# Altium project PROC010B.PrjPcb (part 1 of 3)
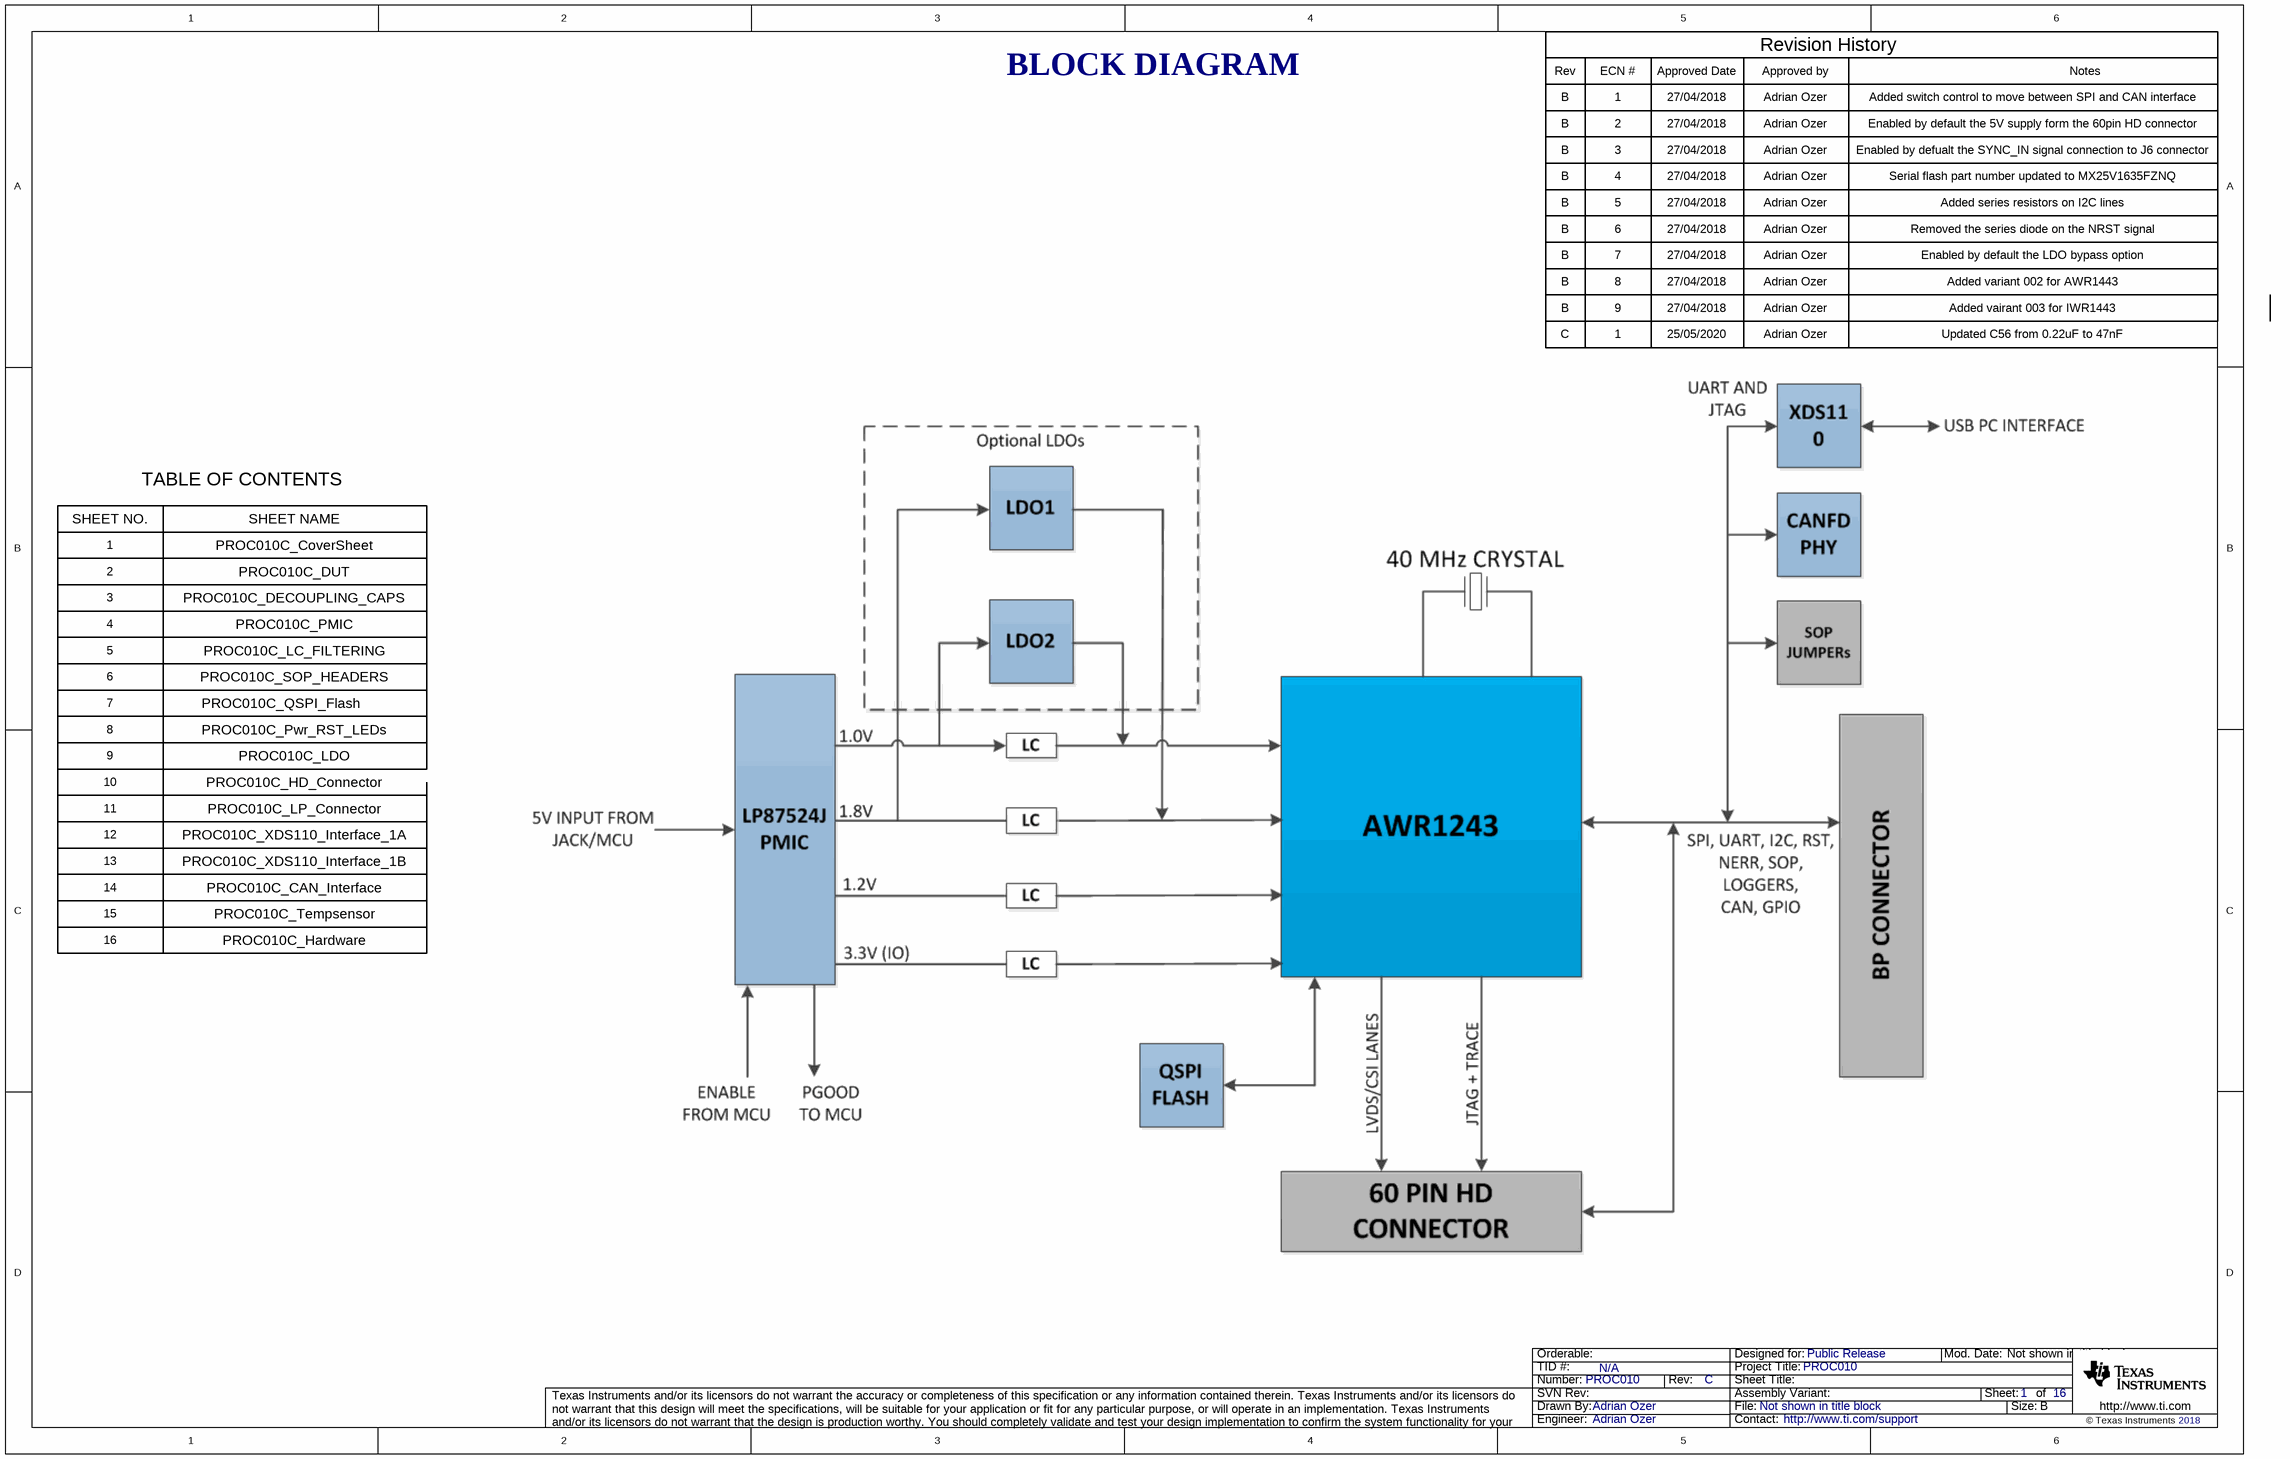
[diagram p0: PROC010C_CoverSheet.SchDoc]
TID: N/A; TechSupport: http://www.ti.com/support; SCH_Rev: C; PRJ_Title: PROC010; PRJ_Number: PROC010; PRJ_Engineer: Adrian Ozer; PRJ_Customer: Public Release; PCB_Rev: B; PCB_Layout: Tessolve; CopyrightYear: 2018
16 sheets, 385 parts. Net scope: flat (ports and power ports of the same name join across sheets).
Board file: PROC010B_PCB.PcbDoc
Sheets:
  PROC010C_CoverSheet.SchDoc
  PROC010C_DUT_Reference.SchDoc
  PROC010C_Decoupling_Caps_Reference.SchDoc
  PROC010C_PMIC_Reference.SchDoc
  PROC010C_LC_Filtering_Reference.SchDoc
  PROC010C_SOP_Headers_Reference.SchDoc
  PROC010C_QSPI_Flash_Reference.SchDoc
  PROC010C_Pwr_RST_LEDs.SchDoc
  PROC010C_LDO.SchDoc
  PROC010C_HD Connector.SchDoc
  PROC010C_LP Connector.SchDoc
  PROC010C_XDS110 Interface_1A.SchDoc
  PROC010C_XDS110 Interface_1B.SchDoc
  PROC010C_CAN Interface.SchDoc
  PROC010C_Tempsensor.SchDoc
  PROC010C_Hardware.SchDoc

## Sheet PROC010C_CoverSheet.SchDoc
size 431 x 279 mm; Date: Not shown in title block; ApprovedBy: Not shown in title block; CheckedBy: Not shown in title block; Author: Not shown in title block; CompanyName: Not shown in title block; DrawnBy: Adrian Ozer; Engineer: Not shown in title block; Organization: Not shown in title block; Address1: Not shown in title block; Address2: Not shown in title block; Address3: Not shown in title block; Address4: Not shown in title block; DocumentNumber: 1; Revision: Use project parameter SCH_Rev; SheetNumber: 1; SheetTotal: 16; PageSetup: Record=PageOptions¦CenterHorizontal=True¦CenterVertical=True¦PrintScale=1.00¦XCorrection=1.00¦YCorrection=1.00¦PrintKind=0¦BorderSize=5000000¦LeftOffset=0¦BottomOffset=0¦Orientation=2¦PaperLength=1000¦PaperWidth=1000¦Scale=100¦PaperSource=15¦PrintQuality=600¦MediaType=1¦DitherType=10¦PaperKind=Letter¦PrintScaleMode=1

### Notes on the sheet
- BLOCK DIAGRAM
- Rev
- B
- ECN #
- 1
- Approved Date
- 27/04/2018
- Approved by
- Adrian Ozer
- Revision History
- Added switch control to move between SPI and CAN interface
- Notes
- 2
- 3
- Enabled by default the 5V supply form the 60pin HD connector
- Enabled by defualt the SYNC_IN signal connection to J6 connector
- 4
- 5
- 6
- Serial flash part number updated to MX25V1635FZNQ
- Added series resistors on I2C lines
- Removed the series diode on the NRST signal
- 7
- 8
- Enabled by default the LDO bypass option
- Added variant 002 for AWR1443
- C
- 9
- 25/05/2020
- Added vairant 003 for IWR1443
- Updated C56 from 0.22uF to 47nF
- TABLE OF CONTENTS
- SHEET NO.
- SHEET NAME
- PROC010C_CoverSheet
- PROC010C_DUT
- PROC010C_DECOUPLING_CAPS
- PROC010C_PMIC
- PROC010C_LC_FILTERING
- PROC010C_SOP_HEADERS
- PROC010C_QSPI_Flash
- PROC010C_Pwr_RST_LEDs
- PROC010C_LDO
- 11
- 10
- PROC010C_HD_Connector
- PROC010C_LP_Connector
- 12
- 13
- 14
- PROC010C_XDS110_Interface_1A
- PROC010C_XDS110_Interface_1B
- PROC010C_CAN_Interface
- 15
- 16
- PROC010C_Tempsensor
- PROC010C_Hardware

## Sheet PROC010C_DUT_Reference.SchDoc
size 431 x 279 mm; Date: Not shown in title block; ApprovedBy: Not shown in title block; CheckedBy: Not shown in title block; Author: Not shown in title block; CompanyName: Not shown in title block; DrawnBy: Adrian Ozer; Engineer: Not shown in title block; Organization: Not shown in title block; Address1: Not shown in title block; Address2: Not shown in title block; Address3: Not shown in title block; Address4: Not shown in title block; DocumentNumber: 2; Revision: Use project parameter SCH_Rev; SheetNumber: 2; SheetTotal: 16; PageSetup: Record=PageOptions¦CenterHorizontal=True¦CenterVertical=True¦PrintScale=1.00¦XCorrection=1.00¦YCorrection=1.00¦PrintKind=0¦BorderSize=5000000¦LeftOffset=0¦BottomOffset=0¦Orientation=2¦PaperLength=1000¦PaperWidth=1000¦Scale=100¦PaperSource=15¦PrintQuality=600¦MediaType=1¦DitherType=10¦PaperKind=Letter¦PrintScaleMode=1
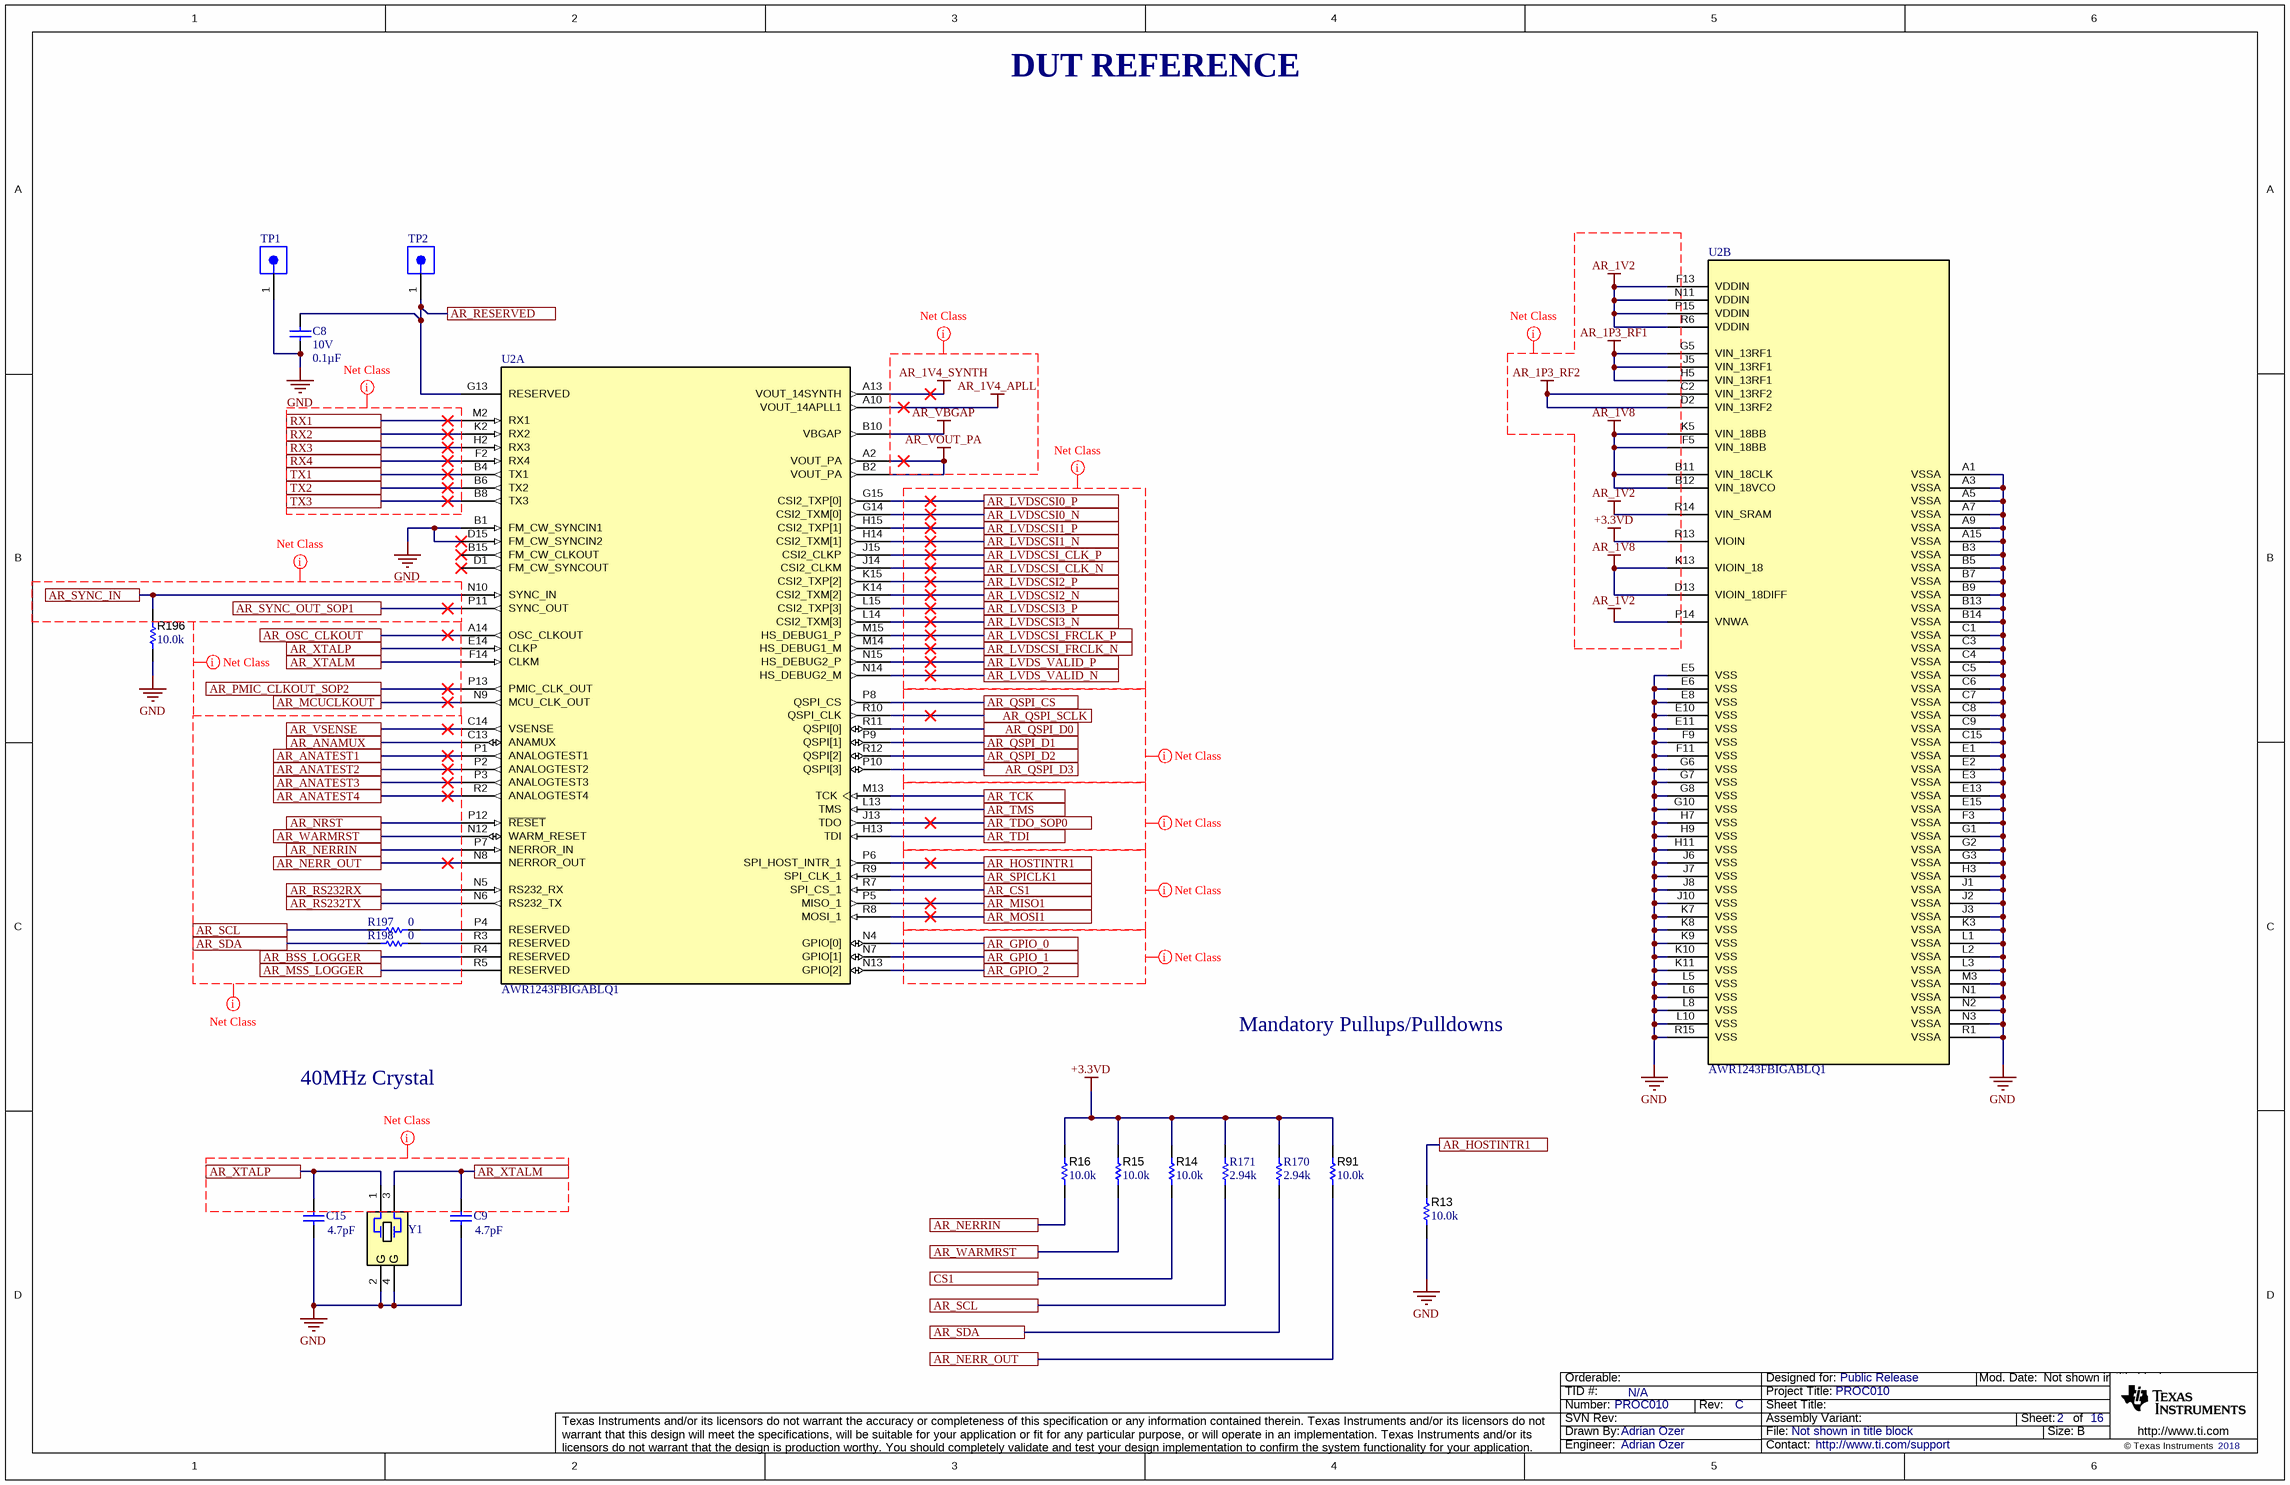
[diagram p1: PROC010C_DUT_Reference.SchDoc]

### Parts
C8  VDC_V: 10V  ValueDisplayed: 0.1µF  [0201_033]  (hidden comment: C0603X7S1A104K030BC)
C9  ValueDisplayed: 4.7pF  [0402]  (hidden comment: GJM1555C1H4R7BB01D)
C15  ValueDisplayed: 4.7pF  [0402]  (hidden comment: GJM1555C1H4R7BB01D)
R13  ValueDisplayed: 10.0k  [0402L]  (hidden comment: CRCW040210K0FKED)
R14  ValueDisplayed: 10.0k  [0402L]  (hidden comment: CRCW040210K0FKED)
R15  ValueDisplayed: 10.0k  [0402L]  (hidden comment: CRCW040210K0FKED)
R16  ValueDisplayed: 10.0k  [0402L]  (hidden comment: CRCW040210K0FKED)
R91  ValueDisplayed: 10.0k  [0402L]  (hidden comment: CRCW040210K0FKED)
R170  ValueDisplayed: 2.94k  [0402]  (hidden comment: CRCW04022K94FKED)
R171  ValueDisplayed: 2.94k  [0402]  (hidden comment: CRCW04022K94FKED)
R196  ValueDisplayed: 10.0k  [0402L]  (hidden comment: CRCW040210K0FKED)
R197  ValueDisplayed: 0  [0201]  (hidden comment: CRCW02010000Z0ED)
R198  ValueDisplayed: 0  [0201]  (hidden comment: CRCW02010000Z0ED)
TP1  TSW-101-17-T-S  [Samtec_TSW-101-17-T-S]  (value not drawn)
TP2  TSW-101-17-T-S  [Samtec_TSW-101-17-T-S]  (value not drawn)
U2  AWR1243FBIGABLQ1  [ABL0161A]  (parts A,B of 2)
Y1  CX3225SA40000D0PTWCC  [Kyocera_CX3225SA]  (value not drawn)

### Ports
AR_ANAMUX, AR_ANATEST1, AR_ANATEST2, AR_ANATEST3, AR_ANATEST4, AR_BSS_LOGGER, AR_CS1, AR_GPIO_0, AR_GPIO_1, AR_GPIO_2, AR_HOSTINTR1, AR_LVDS_VALID_N, AR_LVDS_VALID_P, AR_LVDSCSI0_N, AR_LVDSCSI0_P, AR_LVDSCSI1_N, AR_LVDSCSI1_P, AR_LVDSCSI2_N, AR_LVDSCSI2_P, AR_LVDSCSI3_N, AR_LVDSCSI3_P, AR_LVDSCSI_CLK_N, AR_LVDSCSI_CLK_P, AR_LVDSCSI_FRCLK_N, AR_LVDSCSI_FRCLK_P, AR_MCUCLKOUT, AR_MISO1, AR_MOSI1, AR_MSS_LOGGER, AR_NERR_OUT, AR_NERRIN, AR_NRST, AR_OSC_CLKOUT, AR_PMIC_CLKOUT_SOP2, AR_QSPI_CS, AR_QSPI_D0, AR_QSPI_D1, AR_QSPI_D2, AR_QSPI_D3, AR_QSPI_SCLK, AR_RESERVED, AR_RS232RX, AR_RS232TX, AR_SCL, AR_SDA, AR_SPICLK1, AR_SYNC_IN, AR_SYNC_OUT_SOP1, AR_TCK, AR_TDI, AR_TDO_SOP0, AR_TMS, AR_VSENSE, AR_WARMRST, AR_XTALM, AR_XTALP, CS1, RX1, RX2, RX3, RX4, TX1, TX2, TX3

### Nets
+3.3VD: R14.2 R15.2 R16.2 R91.2 R170.2 R171.2 U2.R13(VIOIN)
AR_1P3_RF1: U2.G5(VIN_13RF1) U2.H5(VIN_13RF1) U2.J5(VIN_13RF1)
AR_1P3_RF2: U2.C2(VIN_13RF2) U2.D2(VIN_13RF2)
AR_1V2: U2.F13(VDDIN) U2.N11(VDDIN) U2.P14(VNWA) U2.P15(VDDIN) U2.R6(VDDIN) U2.R14(VIN_SRAM)
AR_1V4_APLL: U2.A10(VOUT_14APLL1)
AR_1V4_SYNTH: U2.A13(VOUT_14SYNTH)
AR_1V8: U2.B11(VIN_18CLK) U2.B12(VIN_18VCO) U2.D13(VIOIN_18DIFF) U2.F5(VIN_18BB) U2.K5(VIN_18BB) U2.K13(VIOIN_18)
AR_VBGAP: U2.B10(VBGAP)
AR_VOUT_PA: U2.A2(VOUT_PA) U2.B2(VOUT_PA)
GND: C8.2 C9.2 C15.1 R13.1 R196.1 TP1.1 U2.A1(VSSA) U2.A3(VSSA) U2.A5(VSSA) U2.A7(VSSA) U2.A9(VSSA) U2.A15(VSSA) U2.B1(FM_CW_SYNCIN1) U2.B3(VSSA) U2.B5(VSSA) U2.B7(VSSA) U2.B9(VSSA) U2.B13(VSSA) U2.B14(VSSA) U2.C1(VSSA) U2.C3(VSSA) U2.C4(VSSA) U2.C5(VSSA) U2.C6(VSSA) U2.C7(VSSA) U2.C8(VSSA) U2.C9(VSSA) U2.C15(VSSA) U2.D15(FM_CW_SYNCIN2) U2.E1(VSSA) U2.E2(VSSA) U2.E3(VSSA) U2.E5(VSS) U2.E6(VSS) U2.E8(VSS) U2.E10(VSS) U2.E11(VSS) U2.E13(VSSA) U2.E15(VSSA) U2.F3(VSSA) U2.F9(VSS) U2.F11(VSS) U2.G1(VSSA) U2.G2(VSSA) U2.G3(VSSA) U2.G6(VSS) U2.G7(VSS) U2.G8(VSS) U2.G10(VSS) U2.H3(VSSA) U2.H7(VSS) U2.H9(VSS) U2.H11(VSS) U2.J1(VSSA) U2.J2(VSSA) U2.J3(VSSA) U2.J6(VSS) U2.J7(VSS) U2.J8(VSS) U2.J10(VSS) U2.K3(VSSA) U2.K7(VSS) U2.K8(VSS) U2.K9(VSS) U2.K10(VSS) U2.K11(VSS) U2.L1(VSSA) U2.L2(VSSA) U2.L3(VSSA) U2.L5(VSS) U2.L6(VSS) U2.L8(VSS) U2.L10(VSS) U2.M3(VSSA) U2.N1(VSSA) U2.N2(VSSA) U2.N3(VSSA) U2.R1(VSSA) U2.R15(VSS) Y1.2(GND) Y1.4(GND)
AR_ANAMUX: U2.C13(ANAMUX) ; port AR_ANAMUX
AR_ANATEST1: U2.P1(ANALOGTEST1) ; port AR_ANATEST1
AR_ANATEST2: U2.P2(ANALOGTEST2) ; port AR_ANATEST2
AR_ANATEST3: U2.P3(ANALOGTEST3) ; port AR_ANATEST3
AR_ANATEST4: U2.R2(ANALOGTEST4) ; port AR_ANATEST4
AR_BSS_LOGGER: U2.R4(RESERVED) ; port AR_BSS_LOGGER
AR_CS1: U2.R7(SPI_CS_1) ; port AR_CS1
AR_GPIO_0: U2.N4(GPIO[0]) ; port AR_GPIO_0
AR_GPIO_1: U2.N7(GPIO[1]) ; port AR_GPIO_1
AR_GPIO_2: U2.N13(GPIO[2]) ; port AR_GPIO_2
AR_HOSTINTR1: R13.2 U2.P6(SPI_HOST_INTR_1) ; port AR_HOSTINTR1
AR_LVDS_VALID_N: U2.N14(HS_DEBUG2_M) ; port AR_LVDS_VALID_N
AR_LVDS_VALID_P: U2.N15(HS_DEBUG2_P) ; port AR_LVDS_VALID_P
AR_LVDSCSI0_N: U2.G14(CSI2_TXM[0]) ; port AR_LVDSCSI0_N
AR_LVDSCSI0_P: U2.G15(CSI2_TXP[0]) ; port AR_LVDSCSI0_P
AR_LVDSCSI1_N: U2.H14(CSI2_TXM[1]) ; port AR_LVDSCSI1_N
AR_LVDSCSI1_P: U2.H15(CSI2_TXP[1]) ; port AR_LVDSCSI1_P
AR_LVDSCSI2_N: U2.K14(CSI2_TXM[2]) ; port AR_LVDSCSI2_N
AR_LVDSCSI2_P: U2.K15(CSI2_TXP[2]) ; port AR_LVDSCSI2_P
AR_LVDSCSI3_N: U2.L14(CSI2_TXM[3]) ; port AR_LVDSCSI3_N
AR_LVDSCSI3_P: U2.L15(CSI2_TXP[3]) ; port AR_LVDSCSI3_P
AR_LVDSCSI_CLK_N: U2.J14(CSI2_CLKM) ; port AR_LVDSCSI_CLK_N
AR_LVDSCSI_CLK_P: U2.J15(CSI2_CLKP) ; port AR_LVDSCSI_CLK_P
AR_LVDSCSI_FRCLK_N: U2.M14(HS_DEBUG1_M) ; port AR_LVDSCSI_FRCLK_N
AR_LVDSCSI_FRCLK_P: U2.M15(HS_DEBUG1_P) ; port AR_LVDSCSI_FRCLK_P
AR_MCUCLKOUT: U2.N9(MCU_CLK_OUT) ; port AR_MCUCLKOUT
AR_MISO1: U2.P5(MISO_1) ; port AR_MISO1
AR_MOSI1: U2.R8(MOSI_1) ; port AR_MOSI1
AR_MSS_LOGGER: U2.R5(RESERVED) ; port AR_MSS_LOGGER
AR_NERR_OUT: R91.1 U2.N8(NERROR_OUT) ; port AR_NERR_OUT
AR_NERRIN: R16.1 U2.P7(NERROR_IN) ; port AR_NERRIN
AR_NRST: U2.P12(~{RESET}) ; port AR_NRST
AR_OSC_CLKOUT: U2.A14(OSC_CLKOUT) ; port AR_OSC_CLKOUT
AR_PMIC_CLKOUT_SOP2: U2.P13(PMIC_CLK_OUT) ; port AR_PMIC_CLKOUT_SOP2
AR_QSPI_CS: U2.P8(QSPI_CS) ; port AR_QSPI_CS
AR_QSPI_D0: U2.R11(QSPI[0]) ; port AR_QSPI_D0
AR_QSPI_D1: U2.P9(QSPI[1]) ; port AR_QSPI_D1
AR_QSPI_D2: U2.R12(QSPI[2]) ; port AR_QSPI_D2
AR_QSPI_D3: U2.P10(QSPI[3]) ; port AR_QSPI_D3
AR_QSPI_SCLK: U2.R10(QSPI_CLK) ; port AR_QSPI_SCLK
AR_RESERVED: C8.1 TP2.1 U2.G13(RESERVED) ; port AR_RESERVED
AR_RS232RX: U2.N5(RS232_RX) ; port AR_RS232RX
AR_RS232TX: U2.N6(RS232_TX) ; port AR_RS232TX
AR_SCL: R171.1 R197.1 ; port AR_SCL
AR_SDA: R170.1 R198.1 ; port AR_SDA
AR_SPICLK1: U2.R9(SPI_CLK_1) ; port AR_SPICLK1
AR_SYNC_IN: R196.2 U2.N10(SYNC_IN) ; port AR_SYNC_IN
AR_SYNC_OUT_SOP1: U2.P11(SYNC_OUT) ; port AR_SYNC_OUT_SOP1
AR_TCK: U2.M13(TCK) ; port AR_TCK
AR_TDI: U2.H13(TDI) ; port AR_TDI
AR_TDO_SOP0: U2.J13(TDO) ; port AR_TDO_SOP0
AR_TMS: U2.L13(TMS) ; port AR_TMS
AR_VSENSE: U2.C14(VSENSE) ; port AR_VSENSE
AR_WARMRST: R15.1 U2.N12(WARM_RESET) ; port AR_WARMRST
AR_XTALM: C9.1 U2.F14(CLKM) Y1.3 ; port AR_XTALM
AR_XTALP: C15.2 U2.E14(CLKP) Y1.1 ; port AR_XTALP
CS1: R14.1 ; port CS1
RX1: U2.M2(RX1) ; port RX1
RX2: U2.K2(RX2) ; port RX2
RX3: U2.H2(RX3) ; port RX3
RX4: U2.F2(RX4) ; port RX4
TX1: U2.B4(TX1) ; port TX1
TX2: U2.B6(TX2) ; port TX2
TX3: U2.B8(TX3) ; port TX3
NetR197_2: R197.2 U2.P4(RESERVED)
NetR198_2: R198.2 U2.R3(RESERVED)

Not connected (* = marked no-connect by the designer): U2 B15(FM_CW_CLKOUT)* D1(FM_CW_SYNCOUT)*

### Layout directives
net class RF: (no net found under the mark)
net class GENERAL: (no net found under the mark)
net class SPI: (no net found under the mark)
net class PWR: +3.3VD, AR_1P3_RF1, AR_1P3_RF2, AR_1V2, AR_1V4_APLL, AR_1V4_SYNTH, AR_1V8, AR_VBGAP, AR_VOUT_PA
net class CLK: (no net found under the mark)
net class LVDS: (no net found under the mark)
net class QSPI: (no net found under the mark)
net class JTAG: (no net found under the mark)

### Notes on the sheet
- DUT REFERENCE
- Mandatory Pullups/Pulldowns
- 40MHz Crystal

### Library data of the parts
C8 = CMP-0078219-1: CAP, CERM, 0.1 µF, 10 V,+/- 10%, X7S, 0201; Manufacturer: TDK; TaMin_C: -55°C; Polarized: N; Green_Lifecycle: NRND; SizeAreaWB_mm2: 2.08; Green_REACh: Passed; U/M: EA; Value: 0.1uF; TaMax_C: 125°C; SizeZ_mm: 0.33; SizeX_mm: 0.6; SizeY_mm: 0.3; Cap_Case: 0201; SizeArea_mm2: 0.18; Cap_F: 100nF; AEC Category: Q200
C9 C15 = CMP-0006367-2: CAP, CERM, 4.7 pF, 50 V, +/- 2%, C0G/NP0, 0402; Manufacturer: MuRata; TaMin_C: -55°C; Polarized: N; SizeAreaWB_mm2: 3; Value1: Unknown; U/M: EA; Value: 4.7pF; TaMax_C: 125°C; SizeZ_mm: 0.6; SizeX_mm: 1; SizeY_mm: 0.5; Value2: 50V; CompType: Capacitor; AEC Category: Q200
R13-R16 R91 = CMP-0025958-3: RES, 10.0 k, 1%, 0.063 W, AEC-Q200 Grade 0, 0402; Manufacturer: Vishay-Dale; Power_W: 63mW; TempCo: 100 ppm/C; Value_Code: 10k0; Value: 10.0k; EIA_Code: E96; Res_ohm: 10k; SizeX_mm: 1; SizeY_mm: 0.5; SizeZ_mm: 0.6; Value2: 0.063W; AEC Qualified: Y; VDC_V: 50V; AEC Category: Q200; AEC Grade: 0
R170 R171 = CMP-0026244-2: RES, 2.94 k, 1%, 0.063 W, AEC-Q200 Grade 0, 0402; Manufacturer: Vishay-Dale; Power_W: 63mW; TempCo: 100 ppm/C; Value_Code: 2k94; Value: 2.94k; EIA_Code: E96; SizeX_mm: 1; SizeY_mm: 0.5; SizeZ_mm: 0.6; Value2: 0.063W; AEC Qualified: Y; VDC_V: 50V; AEC Category: Q200; AEC Grade: 0
R196 = CMP-0025958-3: RES, 10.0 k, 1%, 0.063 W, AEC-Q200 Grade 0, 0402; Manufacturer: Vishay-Dale; Power_W: 63mW; TempCo: 100 ppm/C; Value_Code: 10k0; Value: 10.0k; EIA_Code: E96; Res_ohm: 10k; SizeX_mm: 1; SizeY_mm: 0.5; SizeZ_mm: 0.6; Value2: 0.063W; CompType: Resistor; AEC Qualified: Y; VDC_V: 50V; AEC Category: Q200; AEC Grade: 0
R197 R198 = CMP-0027008-4: RES, 0, 5%, 0.05 W, 0201; Manufacturer: Vishay-Dale; Power_W: 50mW; TempCo: ppm/C; Value_Code: 0000; Value: 0; EIA_Code: E24; SizeX_mm: 0.6; SizeY_mm: 0.3; SizeZ_mm: 0.26; Value2: 0.05W; SizeArea_mm2: 0.18; AEC Qualified: N; AEC Category: Q200
TP1 TP2 = CMP-0055993-1: Header, 100mil, 1x1, Tin, TH; Manufacturer: Samtec; Cert_VDE: N; CNHeader: FALSE; Current_A: 6.3A; Green_Lifecycle: Active; Gender: Male; Cert_CSA: Y; Green_REACh: Passed; Voltage_V: 550V; Row_Count: 1; Pitch_mm: 2.54
U2 = CMP-0081285-1: Single Chip 77 and 79 GHz FMCW Transceiver, ABL0161A (FCBGA-161); Alternate PartNumber: AWR1243FBIGABLRQ1; Alternate Manufacturer: Texas Instruments; SizeAreaWB_mm2: 153.76; SizeZ_mm: 1.17; SizeX_mm: 10.4; SizeArea_mm2: 108.16; CompType: IC; AEC Qualified: N; AEC Category: Q200
Y1 = CMP-0004694-3: Crystal, 40 MHz, 8pF, SMD; Manufacturer: Kyocera; TaMin_C: -40°C; Frequency Stability: +/-200ppm; SizeAreaWB_mm2: 14.7; Frequency_Fixed: 40MHz; TaMax_C: 125°C; SizeZ_mm: 0.8; SizeX_mm: 2.5; SizeY_mm: 3.2; SizeArea_mm2: 8

## Sheet PROC010C_Decoupling_Caps_Reference.SchDoc
size 431 x 279 mm; Date: Not shown in title block; ApprovedBy: Not shown in title block; CheckedBy: Not shown in title block; Author: Not shown in title block; CompanyName: Not shown in title block; DrawnBy: Adrian Ozer; Engineer: Not shown in title block; Organization: Not shown in title block; Address1: Not shown in title block; Address2: Not shown in title block; Address3: Not shown in title block; Address4: Not shown in title block; DocumentNumber: 3; Revision: Use project parameter SCH_Rev; SheetNumber: 3; SheetTotal: 16; PageSetup: Record=PageOptions¦CenterHorizontal=True¦CenterVertical=True¦PrintScale=1.00¦XCorrection=1.00¦YCorrection=1.00¦PrintKind=0¦BorderSize=5000000¦LeftOffset=0¦BottomOffset=0¦Orientation=2¦PaperLength=1000¦PaperWidth=1000¦Scale=100¦PaperSource=15¦PrintQuality=600¦MediaType=1¦DitherType=10¦PaperKind=Letter¦PrintScaleMode=1
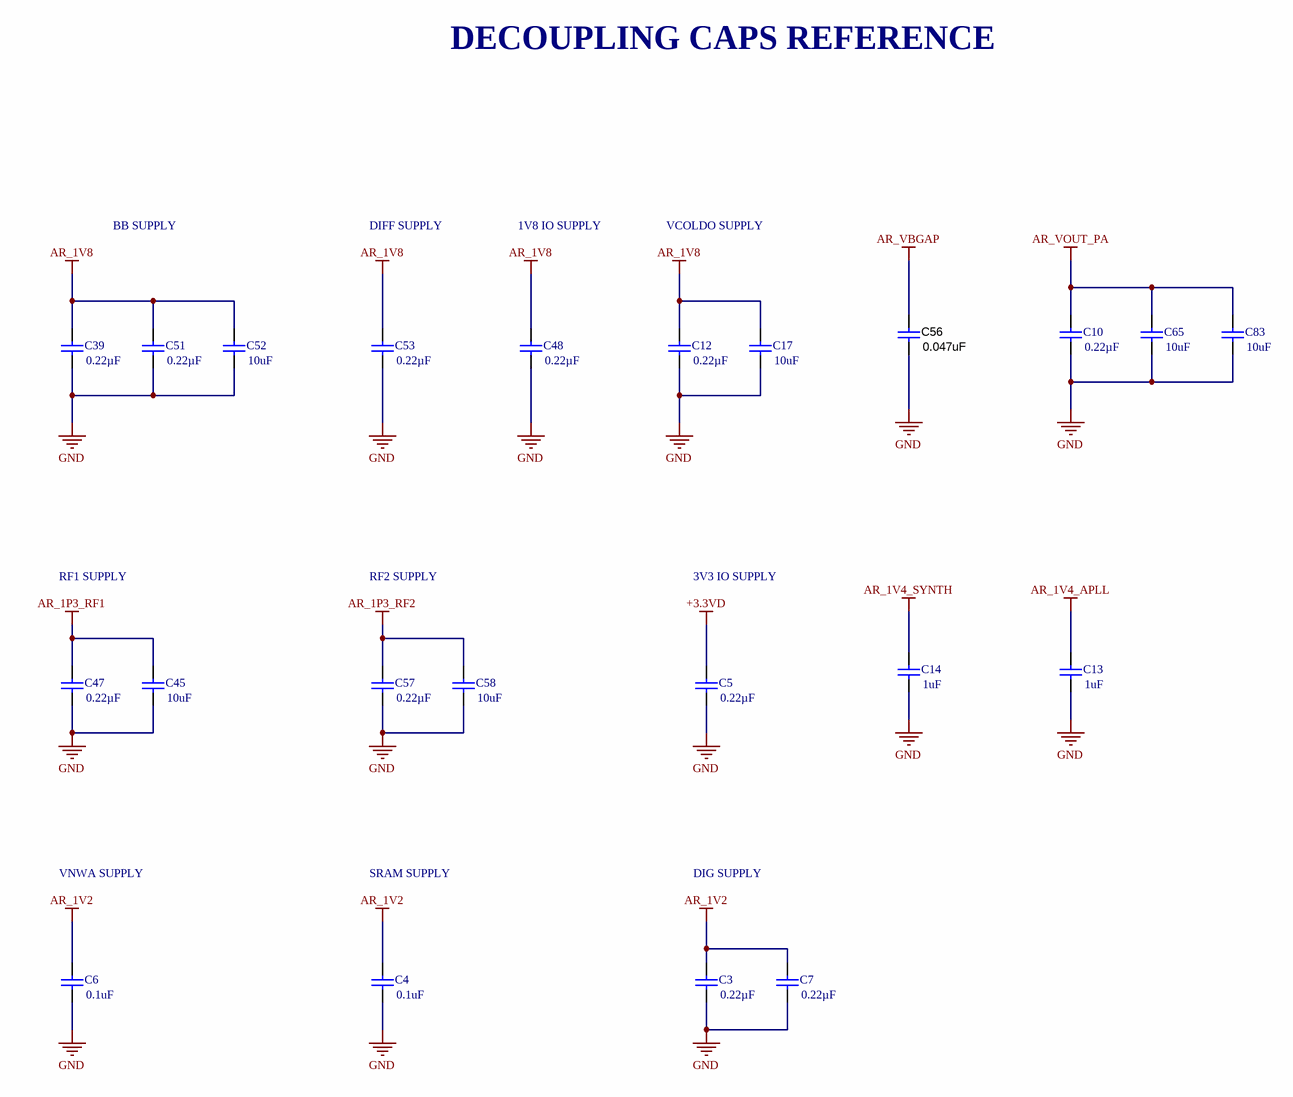
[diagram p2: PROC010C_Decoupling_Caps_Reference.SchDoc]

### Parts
C3  ValueDisplayed: 0.22µF  [0402L]  (hidden comment: GCM155R71C224KE02D)
C4  ValueDisplayed: 0.1uF  [0402L]  (hidden comment: GCM155R71C104KA55D)
C5  ValueDisplayed: 0.22µF  [0402L]  (hidden comment: GCM155R71C224KE02D)
C6  ValueDisplayed: 0.1uF  [0402]  (hidden comment: GCM155R71C104KA55D)
C7  ValueDisplayed: 0.22µF  [0402L]  (hidden comment: GCM155R71C224KE02D)
C10  ValueDisplayed: 0.22µF  [0402]  (hidden comment: GCM155R71C224KE02D)
C12  ValueDisplayed: 0.22µF  [0402]  (hidden comment: GCM155R71C224KE02D)
C13  ValueDisplayed: 1uF  [0603]  (hidden comment: GCM188R71C105KA64D)
C14  ValueDisplayed: 1uF  [0603]  (hidden comment: GCM188R71C105KA64D)
C17  ValueDisplayed: 10uF  [0805_HV]  (hidden comment: GCM21BR71A106KE22L)
C39  ValueDisplayed: 0.22µF  [0402L]  (hidden comment: GCM155R71C224KE02D)
C45  ValueDisplayed: 10uF  [0805_HV1]  (hidden comment: GCM21BR71A106KE22L)
C47  ValueDisplayed: 0.22µF  [0402L]  (hidden comment: GCM155R71C224KE02D)
C48  ValueDisplayed: 0.22µF  [0402]  (hidden comment: GCM155R71C224KE02D)
C51  ValueDisplayed: 0.22µF  [0402]  (hidden comment: GCM155R71C224KE02D)
C52  ValueDisplayed: 10uF  [0805_HV]  (hidden comment: GCM21BR71A106KE22L)
C53  ValueDisplayed: 0.22µF  [0402]  (hidden comment: GCM155R71C224KE02D)
C56  ValueDisplayed: 0.047uF  [0402]  (hidden comment: CGA2B3X7R1H473K050BB)
C57  ValueDisplayed: 0.22µF  [0402]  (hidden comment: GCM155R71C224KE02D)
C58  ValueDisplayed: 10uF  [0805]  (hidden comment: GCM21BR71A106KE22L)
C65  ValueDisplayed: 10uF  [0805_HV]  (hidden comment: GCM21BR71A106KE22L)
C83  ValueDisplayed: 10uF  [0805_HV]  (hidden comment: GCM21BR71A106KE22L)

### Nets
+3.3VD: C5.1
AR_1P3_RF1: C45.1 C47.1
AR_1P3_RF2: C57.1 C58.1
AR_1V2: C3.1 C4.1 C6.1 C7.1
AR_1V4_APLL: C13.1
AR_1V4_SYNTH: C14.1
AR_1V8: C12.1 C17.1 C39.1 C48.1 C51.1 C52.1 C53.1
AR_VBGAP: C56.1
AR_VOUT_PA: C10.1 C65.1 C83.1
GND: C3.2 C4.2 C5.2 C6.2 C7.2 C10.2 C12.2 C13.2 C14.2 C17.2 C39.2 C45.2 C47.2 C48.2 C51.2 C52.2 C53.2 C56.2 C57.2 C58.2 C65.2 C83.2

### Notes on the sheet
- DECOUPLING CAPS REFERENCE
- BB SUPPLY
- DIFF SUPPLY
- 1V8 IO SUPPLY
- VCOLDO SUPPLY
- RF1 SUPPLY
- RF2 SUPPLY
- 3V3 IO SUPPLY
- VNWA SUPPLY
- SRAM SUPPLY
- DIG SUPPLY

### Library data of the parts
C3 C5 C7 C39 C47 = CMP-0078265-1: CAP, CERM, 0.22 µF, 16 V,+/- 10%, X7R, AEC-Q200 Grade 1, 0402; Manufacturer: MuRata; TaMin_C: -55°C; Polarized: N; SizeAreaWB_mm2: 3; U/M: EA; Value: 0.22uF; TaMax_C: 125°C; SizeZ_mm: 0.6; SizeX_mm: 1; SizeY_mm: 0.5; Cap_Case: 0402; Value2: 16V; CompType: Capacitor; AEC Qualified: Y; Cap_F: 220nF; AEC Category: Q200
C4 = CMP-0006351-2: CAP, CERM, 0.1 uF, 16 V, +/- 10%, X7R, 0402; Manufacturer: MuRata; TaMin_C: -55°C; Polarized: N; SizeAreaWB_mm2: 3; Value1: Unknown; U/M: EA; Value: 0.1uF; TaMax_C: 125°C; SizeZ_mm: 0.6; SizeX_mm: 1; SizeY_mm: 0.5; Cap_Case: 0402; Value2: 16V; CompType: Capacitor; Cap_F: 100nF; AEC Category: Q200
C6 = CMP-0006351-2: CAP, CERM, 0.1 uF, 16 V, +/- 10%, X7R, 0402; Manufacturer: MuRata; TaMin_C: -55°C; Polarized: N; SizeAreaWB_mm2: 3; Value1: Unknown; U/M: EA; Value: 0.1uF; TaMax_C: 125°C; SizeZ_mm: 0.6; SizeX_mm: 1; SizeY_mm: 0.5; Value2: 16V; Cap_F: 100nF; AEC Category: Q200
C10 C12 C48 C51 C53 C57 = CMP-0078265-1: CAP, CERM, 0.22 µF, 16 V,+/- 10%, X7R, AEC-Q200 Grade 1, 0402; Manufacturer: MuRata; TaMin_C: -55°C; Polarized: N; SizeAreaWB_mm2: 3; U/M: EA; Value: 0.22uF; TaMax_C: 125°C; SizeZ_mm: 0.6; SizeX_mm: 1; SizeY_mm: 0.5; Value2: 16V; AEC Qualified: Y; Cap_F: 220nF; AEC Category: Q200
C13 C14 = CMP-0007136-5: CAP, CERM, 1 uF, 16 V, +/- 10%, X7R, AEC-Q200 Grade 1, 0603; Manufacturer: MuRata; TaMin_C: -55°C; Polarized: N; SizeAreaWB_mm2: 4.68; Value1: Unknown; U/M: EA; Value: 1uF; TaMax_C: 125°C; SizeZ_mm: 1; SizeX_mm: 1.6; SizeY_mm: 0.8; Value2: 16V; SizeArea_mm2: 1.28; AEC Qualified: Y; Cap_F: 1µF; AEC Category: Q200
C17 C52 C65 C83 = CMP-0008017-2: CAP, CERM, 10 uF, 10 V, +/- 10%, X7R, 0805; Manufacturer: MuRata; TaMin_C: -55°C; Polarized: N; SizeAreaWB_mm2: 6.75; Value1: Unknown; U/M: EA; Value: 10uF; TaMax_C: 125°C; SizeZ_mm: 1.45; SizeX_mm: 2; SizeY_mm: 1.25; Cap_Case: 0805; Value2: 10V; SizeArea_mm2: 2.5; Cap_F: 10µF; AEC Category: Q200
C45 = CMP-0008017-2: CAP, CERM, 10 uF, 10 V, +/- 10%, X7R, 0805; Manufacturer: MuRata; TaMin_C: -55°C; Polarized: N; SizeAreaWB_mm2: 6.75; Value1: Unknown; U/M: EA; Value: 10uF; TaMax_C: 125°C; SizeZ_mm: 1.45; SizeX_mm: 2; SizeY_mm: 1.25; Cap_Case: 0805; Value2: 10V; SizeArea_mm2: 2.5; CompType: Capacitor; Cap_F: 10µF; AEC Category: Q200
C56 = CMP-0006330-2: CAP, CERM, 0.047 uF, 50 V, +/- 10%, X7R, AEC-Q200 Grade 1, 0402; Manufacturer: TDK; TaMin_C: -55°C; ESR_ohm: 0.06407; Polarized: N; SizeAreaWB_mm2: 3; Value1: 0.06407 ohm; U/M: EA; TaMax_C: 125°C; SizeZ_mm: 0.6; SizeX_mm: 1; SizeY_mm: 0.5; Value2: 50V; AEC Qualified: Y; Cap_F: 47nF; IRMS_A: 646.122mA; AEC Category: Q200
C58 = CMP-0008017-2: CAP, CERM, 10 uF, 10 V, +/- 10%, X7R, 0805; Manufacturer: MuRata; TaMin_C: -55°C; Polarized: N; SizeAreaWB_mm2: 6.75; Value1: Unknown; U/M: EA; Value: 10uF; TaMax_C: 125°C; SizeZ_mm: 1.45; SizeX_mm: 2; SizeY_mm: 1.25; Value2: 10V; SizeArea_mm2: 2.5; CompType: Capacitor; Cap_F: 10µF; AEC Category: Q200

## Sheet PROC010C_PMIC_Reference.SchDoc: PMIC
size 431 x 279 mm; Date: Not shown in title block; ApprovedBy: Not shown in title block; CheckedBy: Not shown in title block; Author: Not shown in title block; CompanyName: Not shown in title block; DrawnBy: Adrian Ozer; Engineer: Not shown in title block; Organization: Not shown in title block; Address1: Not shown in title block; Address2: Not shown in title block; Address3: Not shown in title block; Address4: Not shown in title block; DocumentNumber: 4; Revision: Use project parameter SCH_Rev; SheetNumber: 4; SheetTotal: 16; PageSetup: Record=PageOptions¦CenterHorizontal=True¦CenterVertical=True¦PrintScale=1.00¦XCorrection=1.00¦YCorrection=1.00¦PrintKind=0¦BorderSize=5000000¦LeftOffset=0¦BottomOffset=0¦Orientation=2¦PaperLength=1000¦PaperWidth=1000¦Scale=100¦PaperSource=15¦PrintQuality=600¦MediaType=1¦DitherType=10¦PaperKind=Letter¦PrintScaleMode=1
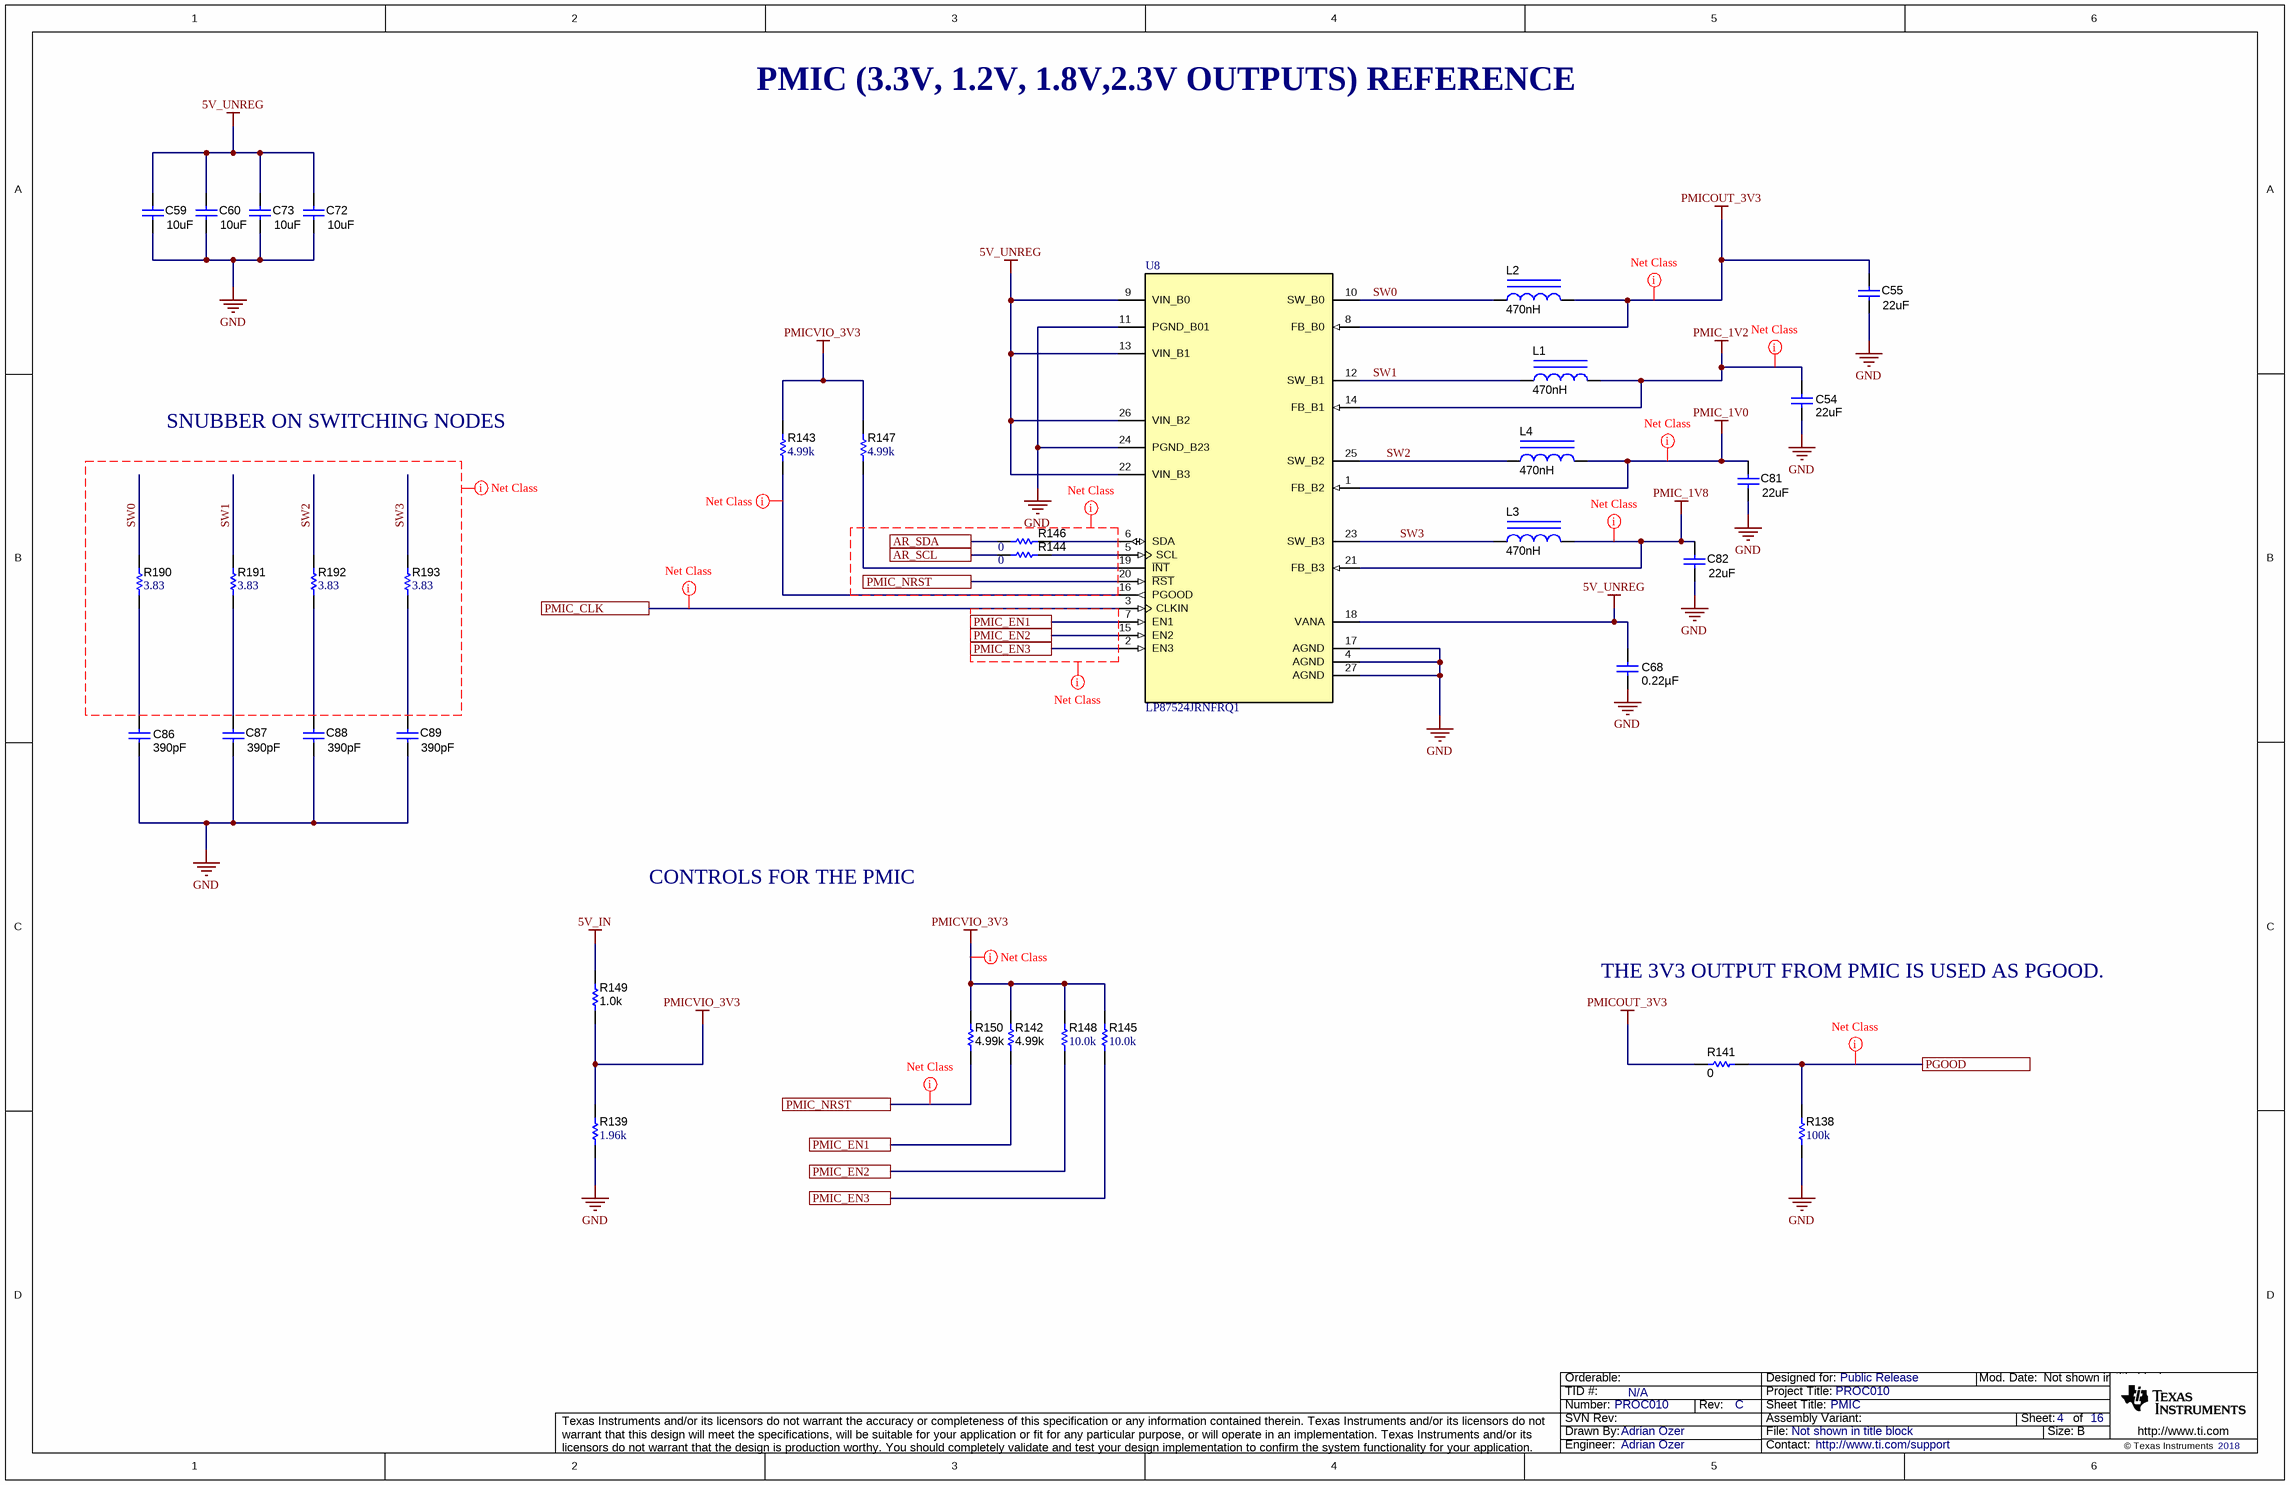
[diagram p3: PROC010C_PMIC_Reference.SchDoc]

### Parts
C54  ValueDisplayed: 22uF  [1206_180]  (hidden comment: GCM31CR71A226KE02)
C55  ValueDisplayed: 22uF  [1206_180]  (hidden comment: GCM31CR71A226KE02)
C59  ValueDisplayed: 10uF  [0805_HV1]  (hidden comment: GCM21BR71A106KE22L)
C60  ValueDisplayed: 10uF  [0805_HV1]  (hidden comment: GCM21BR71A106KE22L)
C68  ValueDisplayed: 0.22µF  [0402L]  (hidden comment: GCM155R71C224KE02D)
C72  ValueDisplayed: 10uF  [0805_HV1]  (hidden comment: GCM21BR71A106KE22L)
C73  ValueDisplayed: 10uF  [0805_HV1]  (hidden comment: GCM21BR71A106KE22L)
C81  ValueDisplayed: 22uF  [1206_180]  (hidden comment: GCM31CR71A226KE02)
C82  ValueDisplayed: 22uF  [1206_180]  (hidden comment: GCM31CR71A226KE02)
C86  ValueDisplayed: 390pF  [0402L]  (hidden comment: CGA2B2NP01H391J050BA)
C87  ValueDisplayed: 390pF  [0402L]  (hidden comment: CGA2B2NP01H391J050BA)
C88  ValueDisplayed: 390pF  [0402L]  (hidden comment: CGA2B2NP01H391J050BA)
C89  ValueDisplayed: 390pF  [0402L]  (hidden comment: CGA2B2NP01H391J050BA)
L1  ValueDisplayed: 470nH  [DFE252012P]  (hidden comment: DFE252012P-R47M=P2)
L2  ValueDisplayed: 470nH  [DFE252012P]  (hidden comment: DFE252012P-R47M=P2)
L3  ValueDisplayed: 470nH  [DFE252012P]  (hidden comment: DFE252012P-R47M=P2)
L4  ValueDisplayed: 470nH  [DFE252012P]  (hidden comment: DFE252012P-R47M=P2)
R138  ValueDisplayed: 100k  [0402L]  (hidden comment: CRCW0402100KFKED)
R139  ValueDisplayed: 1.96k  [0402L]  (hidden comment: CRCW04021K96FKED)
R141  ValueDisplayed: 0  [0402L]  (hidden comment: ERJ-2GE0R00X)
R142  ValueDisplayed: 4.99k  [0402L]  (hidden comment: ERJ-2RKF4991X)
R143  ValueDisplayed: 4.99k  [0402L]  (hidden comment: CRCW04024K99FKED)
R144  ValueDisplayed: 0  [0201_Silk]  (hidden comment: CRCW02010000Z0ED)
R145  ValueDisplayed: 10.0k  [0402L]  (hidden comment: CRCW040210K0FKED)
R146  ValueDisplayed: 0  [0201_Silk]  (hidden comment: CRCW02010000Z0ED)
R147  ValueDisplayed: 4.99k  [0402L]  (hidden comment: CRCW04024K99FKED)
R148  ValueDisplayed: 10.0k  [0402L]  (hidden comment: CRCW040210K0FKED)
R149  ValueDisplayed: 1.0k  [0402L]  (hidden comment: ERJ-2GEJ102X)
R150  ValueDisplayed: 4.99k  [0402L]  (hidden comment: ERJ-2RKF4991X)
R190  ValueDisplayed: 3.83  [0402L]  (hidden comment: CRCW04023R83FKED)
R191  ValueDisplayed: 3.83  [0402L]  (hidden comment: CRCW04023R83FKED)
R192  ValueDisplayed: 3.83  [0402L]  (hidden comment: CRCW04023R83FKED)
R193  ValueDisplayed: 3.83  [0402L]  (hidden comment: CRCW04023R83FKED)
U8  LP87524JRNFRQ1  [RNF0026C]

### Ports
AR_SCL, AR_SDA, PGOOD, PMIC_CLK, PMIC_EN1, PMIC_EN2, PMIC_EN3, PMIC_NRST

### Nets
5V_IN: R149.2
5V_UNREG: C59.2 C60.2 C68.2 C72.2 C73.2 U8.9(VIN_B0) U8.13(VIN_B1) U8.18(VANA) U8.22(VIN_B3) U8.26(VIN_B2)
GND: C54.1 C55.1 C59.1 C60.1 C68.1 C72.1 C73.1 C81.1 C82.1 C86.1 C87.1 C88.1 C89.1 R138.1 R139.1 U8.4(AGND) U8.11(PGND_B01) U8.17(AGND) U8.24(PGND_B23) U8.27(AGND)
PMIC_1V0: C81.2 L4.2 U8.1(FB_B2)
PMIC_1V2: C54.2 L1.2 U8.14(FB_B1)
PMIC_1V8: C82.2 L3.2 U8.21(FB_B3)
PMICOUT_3V3: C55.2 L2.2 R141.1 U8.8(FB_B0)
PMICVIO_3V3: R139.2 R142.2 R143.2 R145.2 R147.2 R148.2 R149.1 R150.1
AR_SCL: R144.1 ; port AR_SCL
AR_SDA: R146.2 ; port AR_SDA
PGOOD: R138.2 R141.2 ; port PGOOD
PMIC_CLK: U8.3(CLKIN) ; port PMIC_CLK
PMIC_EN1: R142.1 U8.7(EN1) ; port PMIC_EN1
PMIC_EN2: R148.1 U8.15(EN2) ; port PMIC_EN2
PMIC_EN3: R145.1 U8.2(EN3) ; port PMIC_EN3
PMIC_NRST: R150.2 U8.20(~{RST}) ; port PMIC_NRST
SW0: L2.1 R190.2 U8.10(SW_B0)
SW1: L1.1 R191.2 U8.12(SW_B1)
SW2: L4.1 R192.2 U8.25(SW_B2)
SW3: L3.1 R193.2 U8.23(SW_B3)
NetC86_2: C86.2 R190.1
NetC87_2: C87.2 R191.1
NetC88_2: C88.2 R192.1
NetC89_2: C89.2 R193.1
NetR143_1: R143.1 U8.16(PGOOD)
NetR144_2: R144.2 U8.5(SCL)
NetR146_1: R146.1 U8.6(SDA)
NetR147_1: R147.1 U8.19(~{INT})

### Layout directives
net class PWR: PGOOD, PMIC_1V0, PMIC_1V2, PMIC_1V8, PMICOUT_3V3, PMICVIO_3V3
net class GENERAL: (no net found under the mark), NetR143_1, PMIC_NRST, SW0, SW1, SW2, SW3
net class CLK: PMIC_CLK

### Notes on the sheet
- PMIC (3.3V, 1.2V, 1.8V,2.3V OUTPUTS) REFERENCE
- SNUBBER ON SWITCHING NODES
- CONTROLS FOR THE PMIC
- THE 3V3 OUTPUT FROM PMIC IS USED AS PGOOD.

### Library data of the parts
C54 = CMP-0008811-2: CAP, CERM, 22 uF, 10 V, +/- 10%, X7R, AEC-Q200 Grade 1, 1206; Manufacturer: MuRata; TaMin_C: -55°C; Polarized: N; SizeAreaWB_mm2: 10.92; Value1: Unknown; U/M: EA; Value: 22uF; TaMax_C: 125°C; SizeZ_mm: 1.8; SizeX_mm: 3.2; SizeY_mm: 1.6; Cap_Case: 1206; Value2: 10V; SizeArea_mm2: 5.12; CompType: Capacitor; AEC Qualified: Y; Cap_F: 22µF; AEC Grade: 1; AEC Category: Q200
C55 C81 C82 = CMP-0008811-2: CAP, CERM, 22 uF, 10 V, +/- 10%, X7R, AEC-Q200 Grade 1, 1206; Manufacturer: MuRata; TaMin_C: -55°C; Polarized: N; SizeAreaWB_mm2: 10.92; Value1: Unknown; U/M: EA; Value: 22uF; TaMax_C: 125°C; SizeZ_mm: 1.8; SizeX_mm: 3.2; SizeY_mm: 1.6; Cap_Case: 1206; Value2: 10V; SizeArea_mm2: 5.12; AEC Qualified: Y; Cap_F: 22µF; AEC Grade: 1; AEC Category: Q200
C59 C60 C72 C73 = CMP-0008017-2: as C45 on sheet PROC010C_Decoupling_Caps_Reference
C68 = CMP-0078265-1: as C3 on sheet PROC010C_Decoupling_Caps_Reference
C86-C89 = CMP-0078223-1: CAP, CERM, 390 pF, 50 V,+/- 5%, C0G/NP0, AEC-Q200 Grade 0, 0402; Manufacturer: TDK; TaMin_C: -55°C; Polarized: N; SizeAreaWB_mm2: 3; U/M: EA; Value: 390pF; TaMax_C: 150°C; SizeZ_mm: 0.6; SizeX_mm: 1; SizeY_mm: 0.5; Cap_Case: 0402; Value2: 50V; AEC Qualified: Y; AEC Grade: 0; AEC Category: Q200
L1-L4 = CMP-0058946-1: Inductor, Shielded, 470 nH, 4.7 A, 0.021 ohm, SMD; Manufacturer: MuRata Toko; Isat: 6.4A @ 30% inductance drop; Irms: 4.7A @ 40C rise; SizeAreaWB_mm2: 10.5; DCR_ohm: 0.021; Value: 470nH; Imax_A: 4.7A; SizeZ_mm: 1.2; SizeX_mm: 2.5; SizeY_mm: 2; SizeArea_mm2: 5; AEC Category: Q200
R138 = CMP-0025950-3: RES, 100 k, 1%, 0.063 W, AEC-Q200 Grade 0, 0402; Manufacturer: Vishay-Dale; Power_W: 63mW; TempCo: 100 ppm/C; Value: 100k; EIA_Code: E96; SizeX_mm: 1; SizeY_mm: 0.5; SizeZ_mm: 0.6; Value2: 0.063W; AEC Qualified: Y; VDC_V: 50V; AEC Category: Q200; AEC Grade: 0
R139 = CMP-0026099-2: RES, 1.96 k, 1%, 0.063 W, AEC-Q200 Grade 0, 0402; Manufacturer: Vishay-Dale; Power_W: 63mW; TempCo: 100 ppm/C; Value_Code: 1k96; Value: 1.96k; EIA_Code: E96; SizeX_mm: 1; SizeY_mm: 0.5; SizeZ_mm: 0.6; Value2: 0.063W; AEC Qualified: Y; VDC_V: 50V; AEC Category: Q200; AEC Grade: 0
R141 = CMP-0026992-2: RES, 0, 5%, 0.063 W, 0402; Manufacturer: Panasonic; Power_W: 63mW; TempCo: 600 ppm/C; Value_Code: 0000; U/M: EA; Value: 0; EIA_Code: E24; SizeX_mm: 1; SizeY_mm: 0.5; SizeZ_mm: 0.6; Value2: 0.063W; VDC_V: 50V; AEC Category: Q200
R142 R150 = CMP-0026701-1: RES, 4.99 k, 1%, 0.1 W, AEC-Q200 Grade 0, 0402; Manufacturer: Panasonic; Power_W: 100mW; TempCo: 100 ppm/C; Value_Code: 4k99; U/M: EA; Value: 4.99k; EIA_Code: E96; SizeX_mm: 1; SizeY_mm: 0.5; SizeZ_mm: 0.6; Value2: 0.1W; AEC Qualified: Y; VDC_V: 50V; AEC Grade: 0; AEC Category: Q200
R143 R147 = CMP-0026414-2: RES, 4.99 k, 1%, 0.063 W, AEC-Q200 Grade 0, 0402; Manufacturer: Vishay-Dale; Power_W: 63mW; TempCo: 100 ppm/C; Value_Code: 4k99; Value: 4.99k; EIA_Code: E96; SizeX_mm: 1; SizeY_mm: 0.5; SizeZ_mm: 0.6; Value2: 0.063W; AEC Qualified: Y; VDC_V: 50V; AEC Category: Q200; AEC Grade: 0
R144 R146 = CMP-0027008-4: as R197 on sheet PROC010C_DUT_Reference
R145 = CMP-0025958-3: as R196 on sheet PROC010C_DUT_Reference
R148 = CMP-0025958-3: as R13 on sheet PROC010C_DUT_Reference
R149 = CMP-0078193-1: RES, 1.0 k, 5%, 0.1 W, AEC-Q200 Grade 0, 0402; Manufacturer: Panasonic; Value_Code: 1k00; SizeArea_mm2: 0.5; AEC Qualified: Y; AEC Category: Q200; Res_ohm: 1k; Value: 1.0k; SizeZ_mm: 0.6; Green_REACh: Passed; EIA_Code: E24; TempCo: 200 ppm/C; AEC Grade: 0; Power_W: 100mW; VDC_V: 50V; Value2: 0.1W; Green_Lifecycle: Active; U/M: EA; SizeX_mm: 1
R190-R193 = CMP-0026363-2: RES, 3.83, 1%, 0.063 W, AEC-Q200 Grade 0, 0402; Manufacturer: Vishay-Dale; Power_W: 63mW; TempCo: 100 ppm/C; Value_Code: 3R83; Value: 3.83; EIA_Code: E96; SizeX_mm: 1; SizeY_mm: 0.5; SizeZ_mm: 0.6; Value2: 0.063W; AEC Qualified: Y; VDC_V: 50V; AEC Category: Q200; AEC Grade: 0
U8 = CMP-0079120-1: 4-A + 2.5-A + Two 1.5-A Buck Converters With Integrated Switches, RNF0026C (VQFN-HR-26); Alternate PartNumber: LP87524JRNFTQ1; Alternate Manufacturer: Texas Instruments; SizeAreaWB_mm2: 27.5; SizeZ_mm: 0.9; SizeX_mm: 4; SizeY_mm: 4.5; SizeArea_mm2: 18; CompType: IC; AEC Qualified: Y; AEC Category: Q200

## Sheet PROC010C_LC_Filtering_Reference.SchDoc
size 431 x 279 mm; Date: Not shown in title block; ApprovedBy: Not shown in title block; CheckedBy: Not shown in title block; Author: Not shown in title block; CompanyName: Not shown in title block; DrawnBy: Adrian Ozer; Engineer: Not shown in title block; Organization: Not shown in title block; Address1: Not shown in title block; Address2: Not shown in title block; Address3: Not shown in title block; Address4: Not shown in title block; DocumentNumber: 5; Revision: Use project parameter SCH_Rev; SheetNumber: 5; SheetTotal: 16; PageSetup: Record=PageOptions¦CenterHorizontal=True¦CenterVertical=True¦PrintScale=1.00¦XCorrection=1.00¦YCorrection=1.00¦PrintKind=0¦BorderSize=5000000¦LeftOffset=0¦BottomOffset=0¦Orientation=2¦PaperLength=1000¦PaperWidth=1000¦Scale=100¦PaperSource=15¦PrintQuality=600¦MediaType=1¦DitherType=10¦PaperKind=Letter¦PrintScaleMode=1
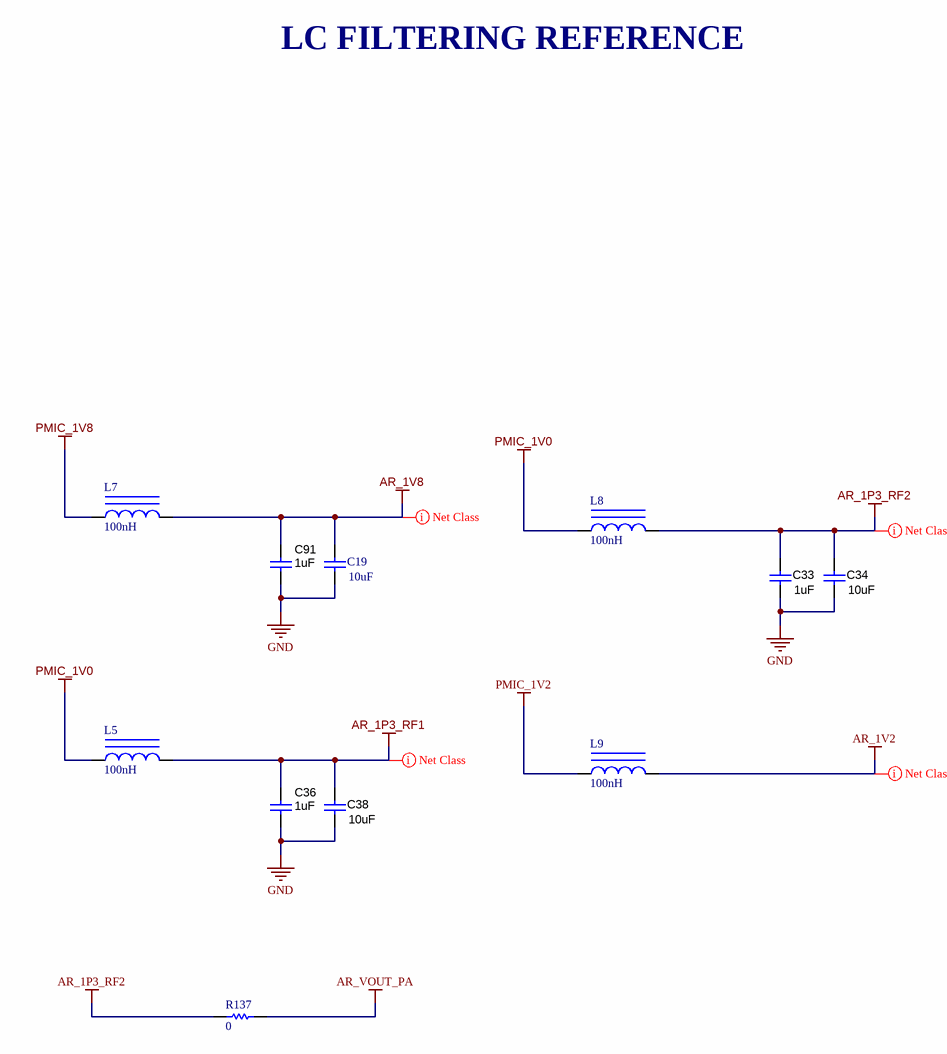
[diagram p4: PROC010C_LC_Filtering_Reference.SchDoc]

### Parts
C19  ValueDisplayed: 10uF  [0805_HV]  (hidden comment: GCM21BR71A106KE22L)
C33  ValueDisplayed: 1uF  [0603]  (hidden comment: GCM188R71C105KA64D)
C34  ValueDisplayed: 10uF  [0805_HV]  (hidden comment: GCM21BR71A106KE22L)
C36  ValueDisplayed: 1uF  [0603]  (hidden comment: GCM188R71C105KA64D)
C38  ValueDisplayed: 10uF  [0805_HV]  (hidden comment: GCM21BR71A106KE22L)
C91  ValueDisplayed: 1uF  [0603]  (hidden comment: GCM188R71C105KA64D)
L5  ValueDisplayed: 100nH  [NLCV32]  (hidden comment: NLCV32T-R10M-EFRD)
L7  ValueDisplayed: 100nH  [NLCV32]  (hidden comment: NLCV32T-R10M-EFRD)
L8  ValueDisplayed: 100nH  [NLCV32]  (hidden comment: NLCV32T-R10M-EFRD)
L9  ValueDisplayed: 100nH  [NLCV32]  (hidden comment: NLCV32T-R10M-EFRD)
R137  ValueDisplayed: 0  [0603]  (hidden comment: MCT06030Z0000ZP500)

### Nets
AR_1P3_RF1: C36.2 C38.2 L5.2
AR_1P3_RF2: C33.2 C34.2 L8.2 R137.1
AR_1V2: L9.2
AR_1V8: C19.1 C91.2 L7.2
AR_VOUT_PA: R137.2
GND: C19.2 C33.1 C34.1 C36.1 C38.1 C91.1
PMIC_1V0: L5.1 L8.1
PMIC_1V2: L9.1
PMIC_1V8: L7.1

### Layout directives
net class PWR: AR_1P3_RF1, AR_1P3_RF2, AR_1V2, AR_1V8

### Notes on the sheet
- LC FILTERING REFERENCE

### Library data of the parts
C19 = CMP-0008017-2: as C17 on sheet PROC010C_Decoupling_Caps_Reference
C33 C36 C91 = CMP-0007136-5: as C13 on sheet PROC010C_Decoupling_Caps_Reference
C34 C38 = CMP-0008017-2: as C45 on sheet PROC010C_Decoupling_Caps_Reference
L5 L7-L9 = CMP-0083745-1: Inductor, Wirewound, Ferrite, 100 nH, 2.85 A, 0.024 ohm, AEC-Q200 Grade 1, SMD; Manufacturer: TDK; Isat: 2.85A @ 10% inductance drop; Irms: 2.85A @ 40C rise; SizeAreaWB_mm2: 13.44; DCR_ohm: 0.024; Value: 100nH; Imax_A: 2.85A; SizeZ_mm: 2.5; SizeX_mm: 3.2; SizeY_mm: 2.2; SizeArea_mm2: 7.04; AEC Qualified: Y; AEC Grade: 1; AEC Category: Q200
R137 = CMP-0025884-3: RES, 0, 5%, 0.125 W, 0603; Manufacturer: Vishay/Beyschlag; Power_W: 125mW; TempCo: ppm/C; Value_Code: 0000; U/M: EA; Value: 0; EIA_Code: E24; SizeX_mm: 1.6; SizeY_mm: 0.8; SizeZ_mm: 1; Value2: 0.125W; SizeArea_mm2: 1.28; CompType: Resistor; AEC Qualified: N; AEC Category: Q200

## Sheet PROC010C_SOP_Headers_Reference.SchDoc
size 431 x 279 mm; Date: Not shown in title block; ApprovedBy: Not shown in title block; CheckedBy: Not shown in title block; Author: Not shown in title block; CompanyName: Not shown in title block; DrawnBy: Adrian Ozer; Engineer: Not shown in title block; Organization: Not shown in title block; Address1: Not shown in title block; Address2: Not shown in title block; Address3: Not shown in title block; Address4: Not shown in title block; DocumentNumber: 6; Revision: Use project parameter SCH_Rev; SheetNumber: 6; SheetTotal: 16; PageSetup: Record=PageOptions¦CenterHorizontal=True¦CenterVertical=True¦PrintScale=1.00¦XCorrection=1.00¦YCorrection=1.00¦PrintKind=0¦BorderSize=5000000¦LeftOffset=0¦BottomOffset=0¦Orientation=2¦PaperLength=1000¦PaperWidth=1000¦Scale=100¦PaperSource=15¦PrintQuality=600¦MediaType=1¦DitherType=10¦PaperKind=Letter¦PrintScaleMode=1
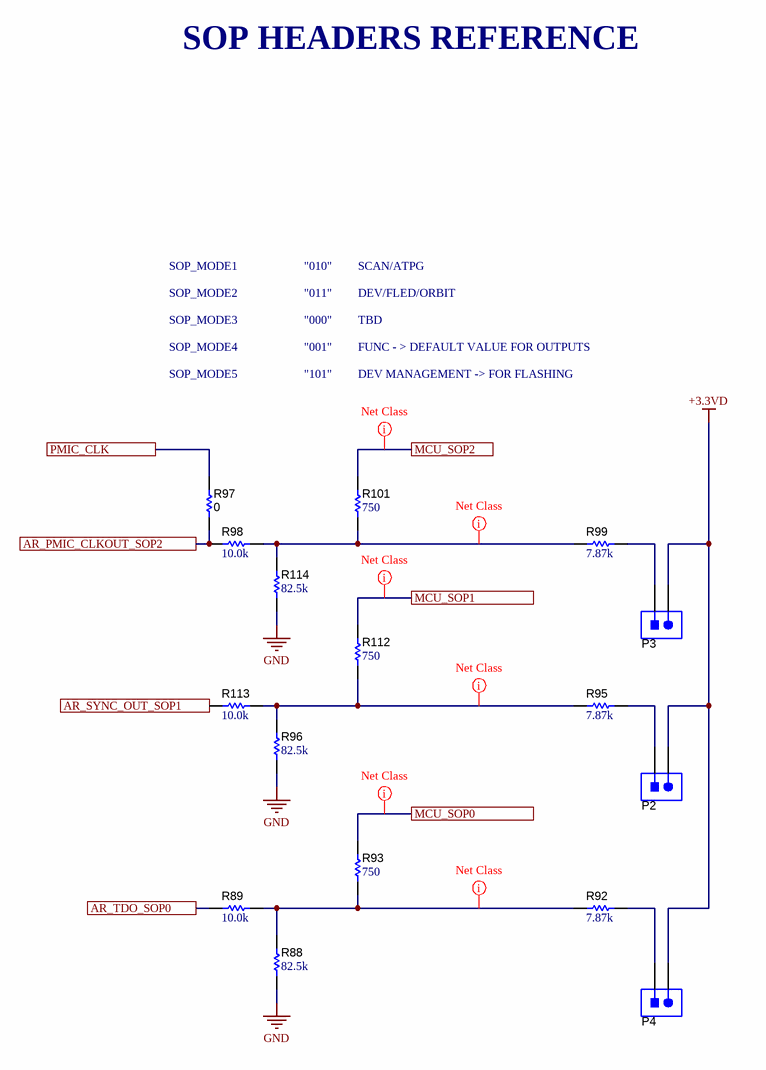
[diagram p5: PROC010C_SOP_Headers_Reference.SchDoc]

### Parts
P2  TSW-102-07-G-S  [TSW-102-07-G-S]  (value not drawn)
P3  TSW-102-07-G-S  [TSW-102-07-G-S]  (value not drawn)
P4  TSW-102-07-G-S  [TSW-102-07-G-S]  (value not drawn)
R88  ValueDisplayed: 82.5k  [0402L]  (hidden comment: CRCW040282K5FKED)
R89  ValueDisplayed: 10.0k  [0402L]  (hidden comment: CRCW040210K0FKED)
R92  ValueDisplayed: 7.87k  [0402L]  (hidden comment: CRCW04027K87FKED)
R93  ValueDisplayed: 750  [0402L]  (hidden comment: CRCW0402750RFKED)
R95  ValueDisplayed: 7.87k  [0402L]  (hidden comment: CRCW04027K87FKED)
R96  ValueDisplayed: 82.5k  [0402L]  (hidden comment: CRCW040282K5FKED)
R97  ValueDisplayed: 0  [0402L]  (hidden comment: ERJ-2GE0R00X)
R98  ValueDisplayed: 10.0k  [0402L]  (hidden comment: CRCW040210K0FKED)
R99  ValueDisplayed: 7.87k  [0402L]  (hidden comment: CRCW04027K87FKED)
R101  ValueDisplayed: 750  [0402L]  (hidden comment: CRCW0402750RFKED)
R112  ValueDisplayed: 750  [0402L]  (hidden comment: CRCW0402750RFKED)
R113  ValueDisplayed: 10.0k  [0402L]  (hidden comment: CRCW040210K0FKED)
R114  ValueDisplayed: 82.5k  [0402L]  (hidden comment: CRCW040282K5FKED)

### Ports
AR_PMIC_CLKOUT_SOP2, AR_SYNC_OUT_SOP1, AR_TDO_SOP0, MCU_SOP0, MCU_SOP1, MCU_SOP2, PMIC_CLK

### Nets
+3.3VD: P2.2 P3.2 P4.2
GND: R88.1 R96.1 R114.1
AR_PMIC_CLKOUT_SOP2: R97.1 R98.1 ; port AR_PMIC_CLKOUT_SOP2
AR_SYNC_OUT_SOP1: R113.1 ; port AR_SYNC_OUT_SOP1
AR_TDO_SOP0: R89.1 ; port AR_TDO_SOP0
MCU_SOP0: R93.2 ; port MCU_SOP0
MCU_SOP1: R112.2 ; port MCU_SOP1
MCU_SOP2: R101.2 ; port MCU_SOP2
PMIC_CLK: R97.2 ; port PMIC_CLK
NetP2_1: P2.1 R95.2
NetP3_1: P3.1 R99.2
NetP4_1: P4.1 R92.2
NetR88_2: R88.2 R89.2 R92.1 R93.1
NetR95_1: R95.1 R96.2 R112.1 R113.2
NetR98_2: R98.2 R99.1 R101.1 R114.2

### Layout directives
net class GENERAL: MCU_SOP0, MCU_SOP1, MCU_SOP2, NetR88_2, NetR95_1, NetR98_2

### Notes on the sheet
- SOP HEADERS REFERENCE
- SOP_MODE1
- "010"
- SCAN/ATPG
- SOP_MODE2
- SOP_MODE3
- "011"
- "000"
- DEV/FLED/ORBIT
- TBD
- SOP_MODE4
- SOP_MODE5
- "001"
- "101"
- FUNC - > DEFAULT VALUE FOR OUTPUTS
- DEV MANAGEMENT -> FOR FLASHING

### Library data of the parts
P2-P4 = CMP-0075405-2: Header, 100mil, 2x1, Gold, TH; Manufacturer: Samtec; Pitch_mm: 2.54; Cert_VDE: N; Gender: Male; Cert_CSA: Y; Voltage_V: 550V; Green_REACh: Passed; Current_A: 6.3A; Green_Lifecycle: Active; Row_Count: 1
R88 R96 = CMP-0026574-2: RES, 82.5 k, 1%, 0.063 W, AEC-Q200 Grade 0, 0402; Manufacturer: Vishay-Dale; Power_W: 63mW; TempCo: 100 ppm/C; Value_Code: 82k5; Value: 82.5k; EIA_Code: E96; SizeX_mm: 1; SizeY_mm: 0.5; SizeZ_mm: 0.6; Value2: 0.063W; AEC Qualified: Y; VDC_V: 50V; AEC Grade: 0; AEC Category: Q200
R89 R98 R113 = CMP-0025958-3: as R196 on sheet PROC010C_DUT_Reference
R92 R95 R99 = CMP-0026557-2: RES, 7.87 k, 1%, 0.063 W, AEC-Q200 Grade 0, 0402; Manufacturer: Vishay-Dale; Power_W: 63mW; TempCo: 100 ppm/C; Value_Code: 7k87; Value: 7.87k; EIA_Code: E96; SizeX_mm: 1; SizeY_mm: 0.5; SizeZ_mm: 0.6; Value2: 0.063W; AEC Qualified: Y; VDC_V: 50V; AEC Grade: 0; AEC Category: Q200
R93 R112 = CMP-0026542-2: RES, 750, 1%, 0.063 W, AEC-Q200 Grade 0, 0402; Manufacturer: Vishay-Dale; Power_W: 63mW; TempCo: 100 ppm/C; Value_Code: 750R; Value: 750; EIA_Code: E96; SizeX_mm: 1; SizeY_mm: 0.5; SizeZ_mm: 0.6; Value2: 0.063W; AEC Qualified: Y; VDC_V: 50V; AEC Grade: 0; AEC Category: Q200
R97 = CMP-0026992-2: RES, 0, 5%, 0.063 W, 0402; Manufacturer: Panasonic; Power_W: 63mW; TempCo: 600 ppm/C; Value_Code: 0000; U/M: EA; Value: 0; EIA_Code: E24; SizeX_mm: 1; SizeY_mm: 0.5; SizeZ_mm: 0.6; Value2: 0.063W; CompType: Resistor; VDC_V: 50V; AEC Category: Q200; INSTALATION: DNP
R101 = CMP-0026542-2: RES, 750, 1%, 0.063 W, AEC-Q200 Grade 0, 0402; Manufacturer: Vishay-Dale; Power_W: 63mW; TempCo: 100 ppm/C; Value_Code: 750R; Value: 750; EIA_Code: E96; SizeX_mm: 1; SizeY_mm: 0.5; SizeZ_mm: 0.6; Value2: 0.063W; CompType: Resistor; AEC Qualified: Y; VDC_V: 50V; AEC Grade: 0; AEC Category: Q200
R114 = CMP-0026574-2: RES, 82.5 k, 1%, 0.063 W, AEC-Q200 Grade 0, 0402; Manufacturer: Vishay-Dale; Power_W: 63mW; TempCo: 100 ppm/C; Value_Code: 82k5; Value: 82.5k; EIA_Code: E96; SizeX_mm: 1; SizeY_mm: 0.5; SizeZ_mm: 0.6; Value2: 0.063W; CompType: Resistor; AEC Qualified: Y; VDC_V: 50V; AEC Grade: 0; AEC Category: Q200

## Sheet PROC010C_QSPI_Flash_Reference.SchDoc: QSPI flash section
size 431 x 279 mm; Date: Not shown in title block; ApprovedBy: Not shown in title block; CheckedBy: Not shown in title block; Author: Not shown in title block; CompanyName: Not shown in title block; DrawnBy: Adrian Ozer; Engineer: Not shown in title block; Organization: Not shown in title block; Address1: Not shown in title block; Address2: Not shown in title block; Address3: Not shown in title block; Address4: Not shown in title block; DocumentNumber: 7; Revision: Use project parameter SCH_Rev; SheetNumber: 7; SheetTotal: 16; PageSetup: Record=PageOptions¦CenterHorizontal=True¦CenterVertical=True¦PrintScale=1.00¦XCorrection=1.00¦YCorrection=1.00¦PrintKind=0¦BorderSize=5000000¦LeftOffset=0¦BottomOffset=0¦Orientation=2¦PaperLength=1000¦PaperWidth=1000¦Scale=100¦PaperSource=15¦PrintQuality=600¦MediaType=1¦DitherType=10¦PaperKind=Letter¦PrintScaleMode=1
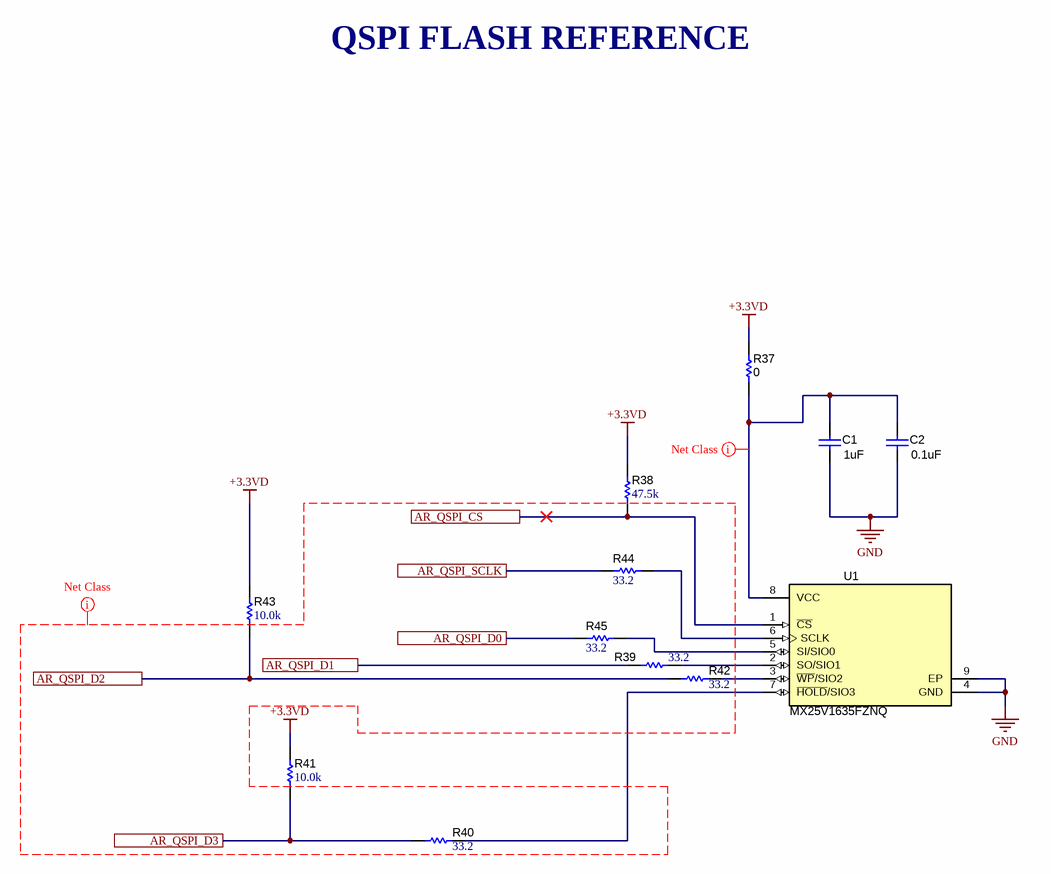
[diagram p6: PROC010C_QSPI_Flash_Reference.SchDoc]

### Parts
C1  ValueDisplayed: 1uF  [0603]  (hidden comment: GCM188R71C105KA64D)
C2  ValueDisplayed: 0.1uF  [0402L]  (hidden comment: CGA2B3X7R1H104K050BB)
R37  ValueDisplayed: 0  [0402L]  (hidden comment: ERJ-2GE0R00X)
R38  ValueDisplayed: 47.5k  [0402L]  (hidden comment: CRCW040247K5FKED)
R39  ValueDisplayed: 33.2  [0201_Silk]  (hidden comment: CRCW020133R2FNED)
R40  ValueDisplayed: 33.2  [0201_Silk]  (hidden comment: CRCW020133R2FNED)
R41  ValueDisplayed: 10.0k  [0402L]  (hidden comment: CRCW040210K0FKED)
R42  ValueDisplayed: 33.2  [0201_Silk]  (hidden comment: CRCW020133R2FNED)
R43  ValueDisplayed: 10.0k  [0402L]  (hidden comment: CRCW040210K0FKED)
R44  ValueDisplayed: 33.2  [0201_Silk]  (hidden comment: CRCW020133R2FNED)
R45  ValueDisplayed: 33.2  [0201_Silk]  (hidden comment: CRCW020133R2FNED)
U1  MX25V1635FZNQ  [WSON-8L_6x5MM_EP]

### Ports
AR_QSPI_CS, AR_QSPI_D0, AR_QSPI_D1, AR_QSPI_D2, AR_QSPI_D3, AR_QSPI_SCLK

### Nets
+3.3VD: R37.1 R38.2 R41.2 R43.2
GND: C1.1 C2.1 U1.4(GND) U1.9(EP)
AR_QSPI_CS: R38.1 U1.1(~{CS}) ; port AR_QSPI_CS
AR_QSPI_D0: R45.2 ; port AR_QSPI_D0
AR_QSPI_D1: R39.1 ; port AR_QSPI_D1
AR_QSPI_D2: R42.1 R43.1 ; port AR_QSPI_D2
AR_QSPI_D3: R40.2 R41.1 ; port AR_QSPI_D3
AR_QSPI_SCLK: R44.2 ; port AR_QSPI_SCLK
NetC1_2: C1.2 C2.2 R37.2 U1.8(VCC)
NetR39_2: R39.2 U1.2(SO/SIO1)
NetR40_1: R40.1 U1.7(~{HOLD}/SIO3)
NetR42_2: R42.2 U1.3(~{WP}/SIO2)
NetR44_1: R44.1 U1.6(SCLK)
NetR45_1: R45.1 U1.5(SI/SIO0)

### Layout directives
net class PWR: NetC1_2
net class QSPI: +3.3VD

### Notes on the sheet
- QSPI FLASH REFERENCE

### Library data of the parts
C1 = CMP-0007136-5: as C13 on sheet PROC010C_Decoupling_Caps_Reference
C2 = CMP-0006325-2: CAP, CERM, 0.1 uF, 50 V, +/- 10%, X7R, AEC-Q200 Grade 1, 0402; Manufacturer: TDK; TaMin_C: -55°C; ESR_ohm: 0.039064; Polarized: N; SizeAreaWB_mm2: 3; Value1: 0.039064 ohm; U/M: EA; Value: 0.1uF; TaMax_C: 125°C; SizeZ_mm: 0.6; SizeX_mm: 1; SizeY_mm: 0.5; Cap_Case: 0402; Value2: 50V; AEC Qualified: Y; Cap_F: 100nF; IRMS_A: 8.14669dA; AEC Category: Q200
R37 = CMP-0026992-2: as R141 on sheet PROC010C_PMIC_Reference
R38 = CMP-0026395-2: RES, 47.5 k, 1%, 0.063 W, AEC-Q200 Grade 0, 0402; Manufacturer: Vishay-Dale; Power_W: 63mW; TempCo: 100 ppm/C; Value_Code: 47k5; Value: 47.5k; EIA_Code: E96; SizeX_mm: 1; SizeY_mm: 0.5; SizeZ_mm: 0.6; Value2: 0.063W; AEC Qualified: Y; VDC_V: 50V; AEC Category: Q200; AEC Grade: 0
R39 R40 R42 R44 R45 = CMP-0027275-3: RES, 33.2, 1%, 0.05 W, 0201; Manufacturer: Vishay-Dale; Power_W: 50mW; TempCo: 200 ppm/C; Value_Code: 33R2; Value: 33.2; EIA_Code: E96; SizeX_mm: 0.6; SizeY_mm: 0.3; SizeZ_mm: 0.26; Value2: 0.05W; SizeArea_mm2: 0.18; AEC Qualified: N; AEC Category: Q200
R41 R43 = CMP-0025958-3: as R13 on sheet PROC010C_DUT_Reference
U1 = CMP-0079267-1: 2.3V-3.6V, 16M-BIT [x 1/x 2/x 4] CMOS FLASH Memory, WSON-8; Manufacturer: Macronix International Co., LTD; SizeArea_mm2: 30; SizeAreaWB_mm2: 56; SizeY_mm: 5; SizeZ_mm: 0.8; SizeX_mm: 6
